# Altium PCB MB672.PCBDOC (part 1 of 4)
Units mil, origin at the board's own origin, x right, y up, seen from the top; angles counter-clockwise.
Board outline 4505 x 6805 mil, 4 copper layers (TopLayer, GND, VCC, BottomLayer); 337 components, 289 nets, 1516 pads, 621 vias.
Unrouted connection lines stored in the file: 46.
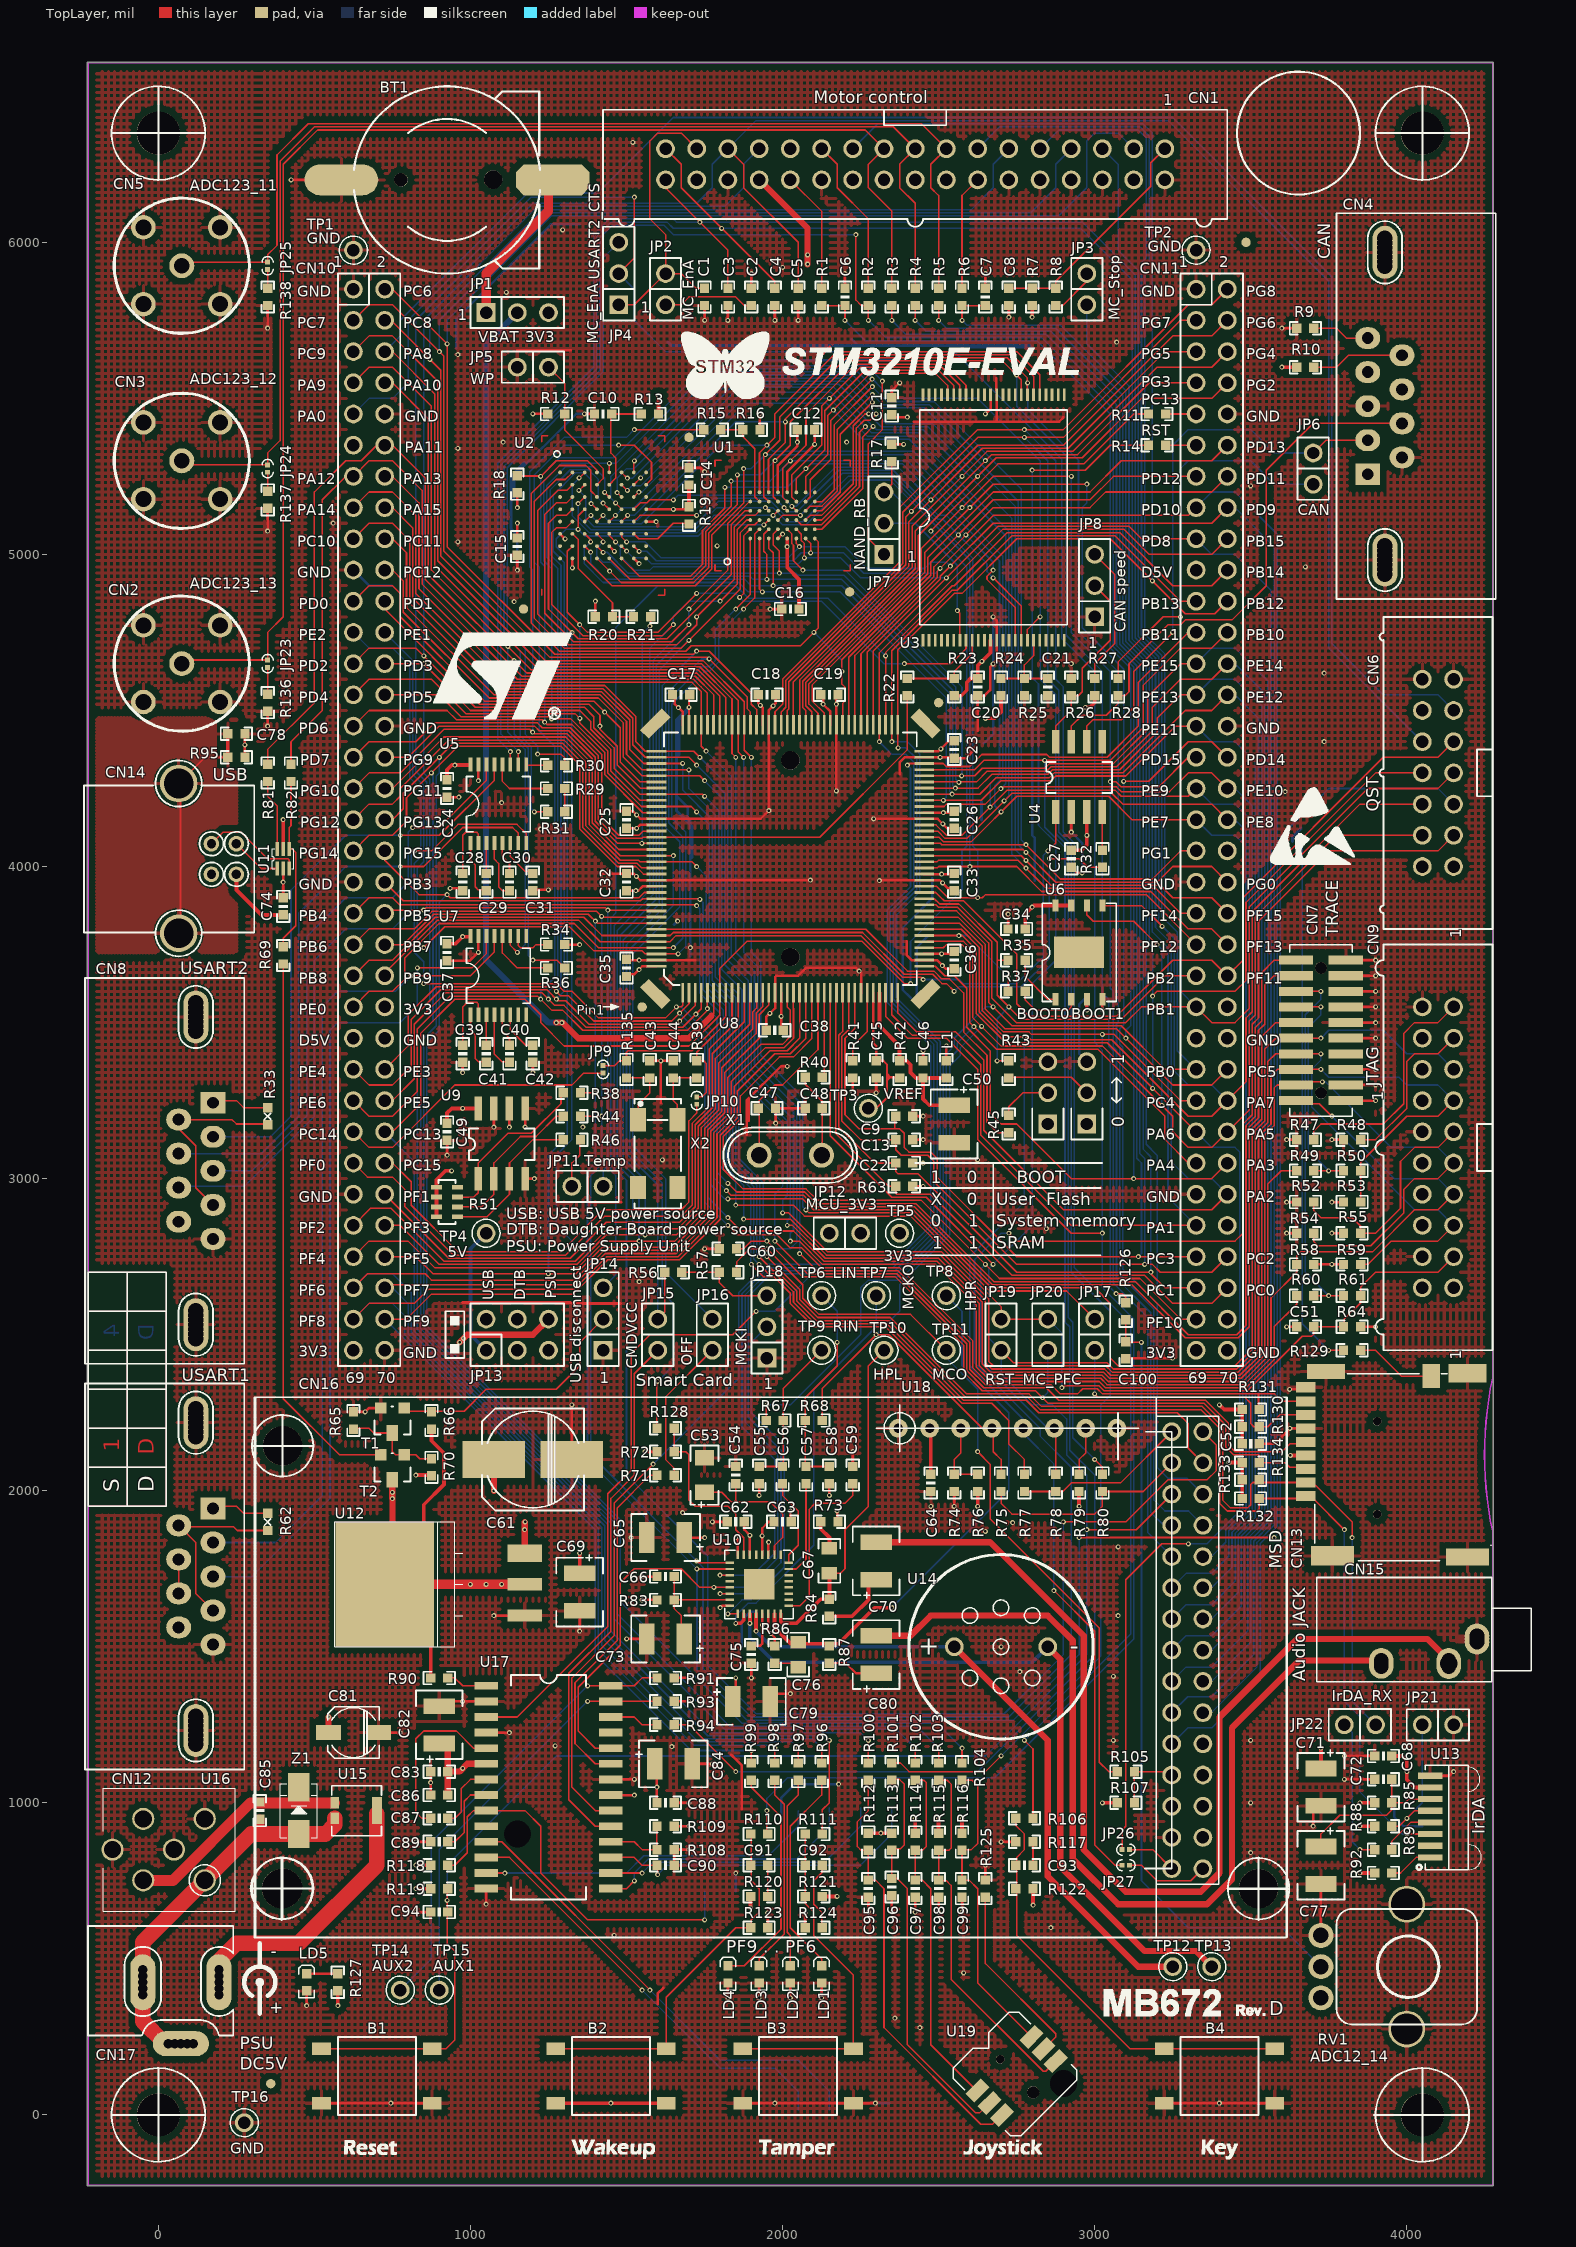
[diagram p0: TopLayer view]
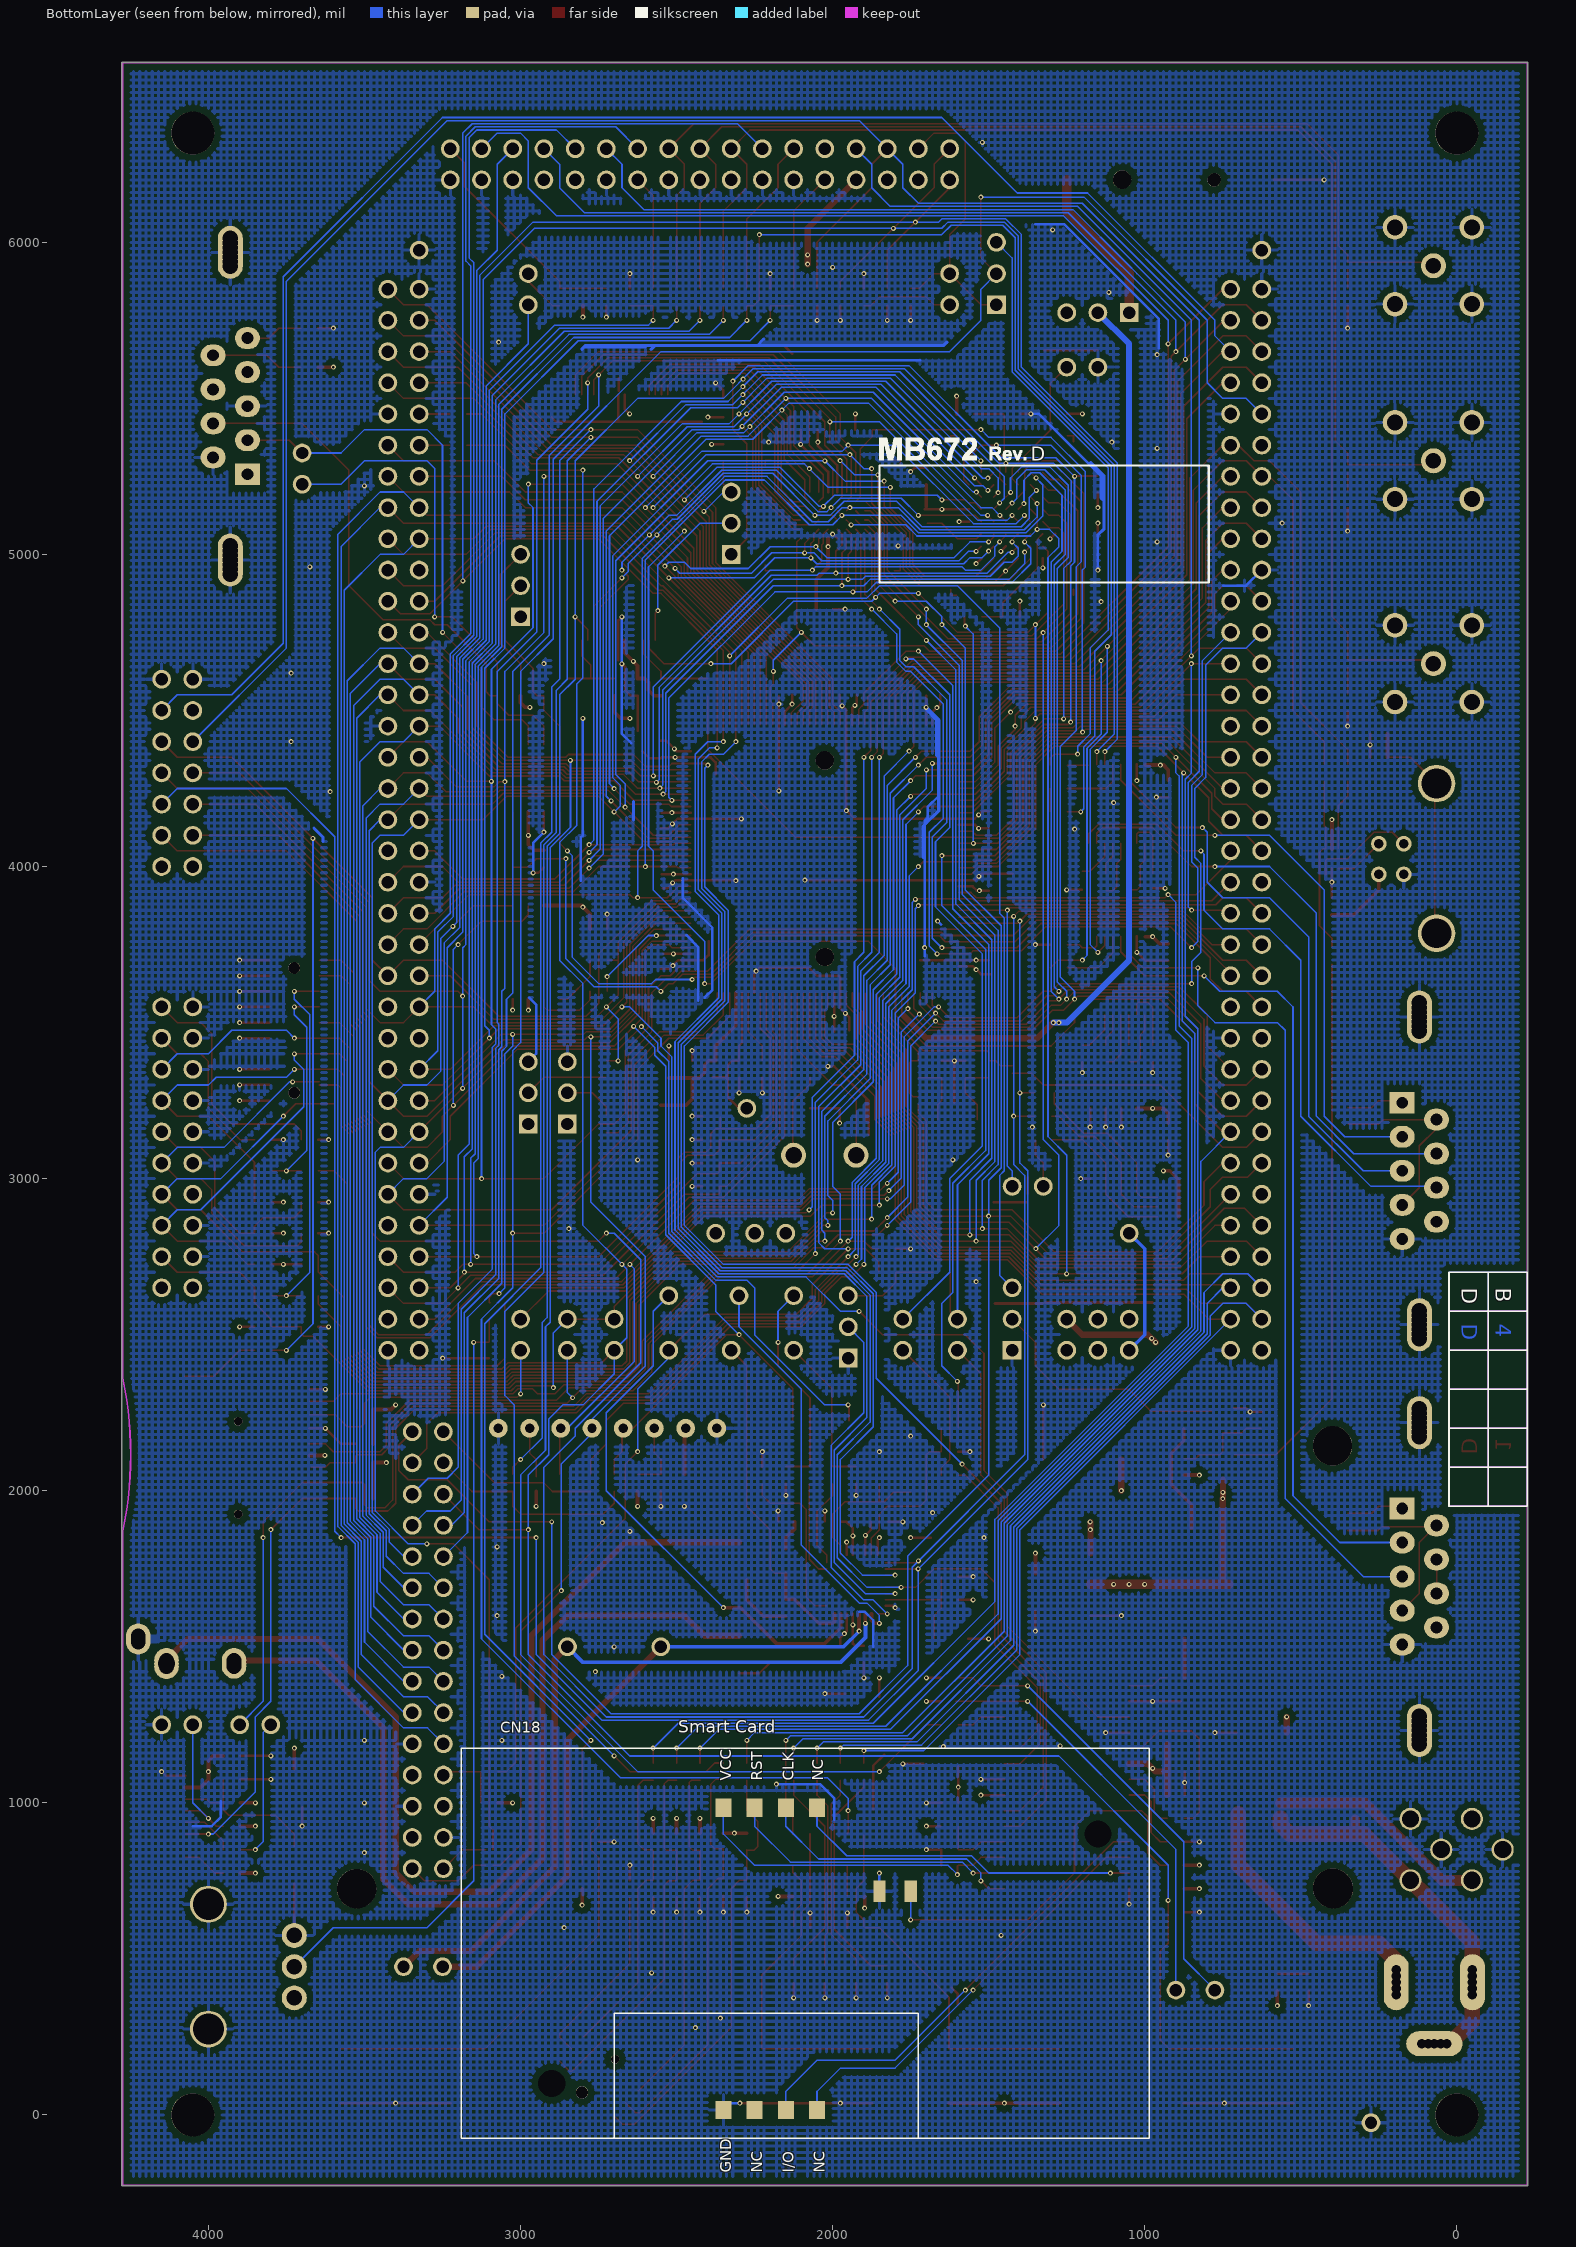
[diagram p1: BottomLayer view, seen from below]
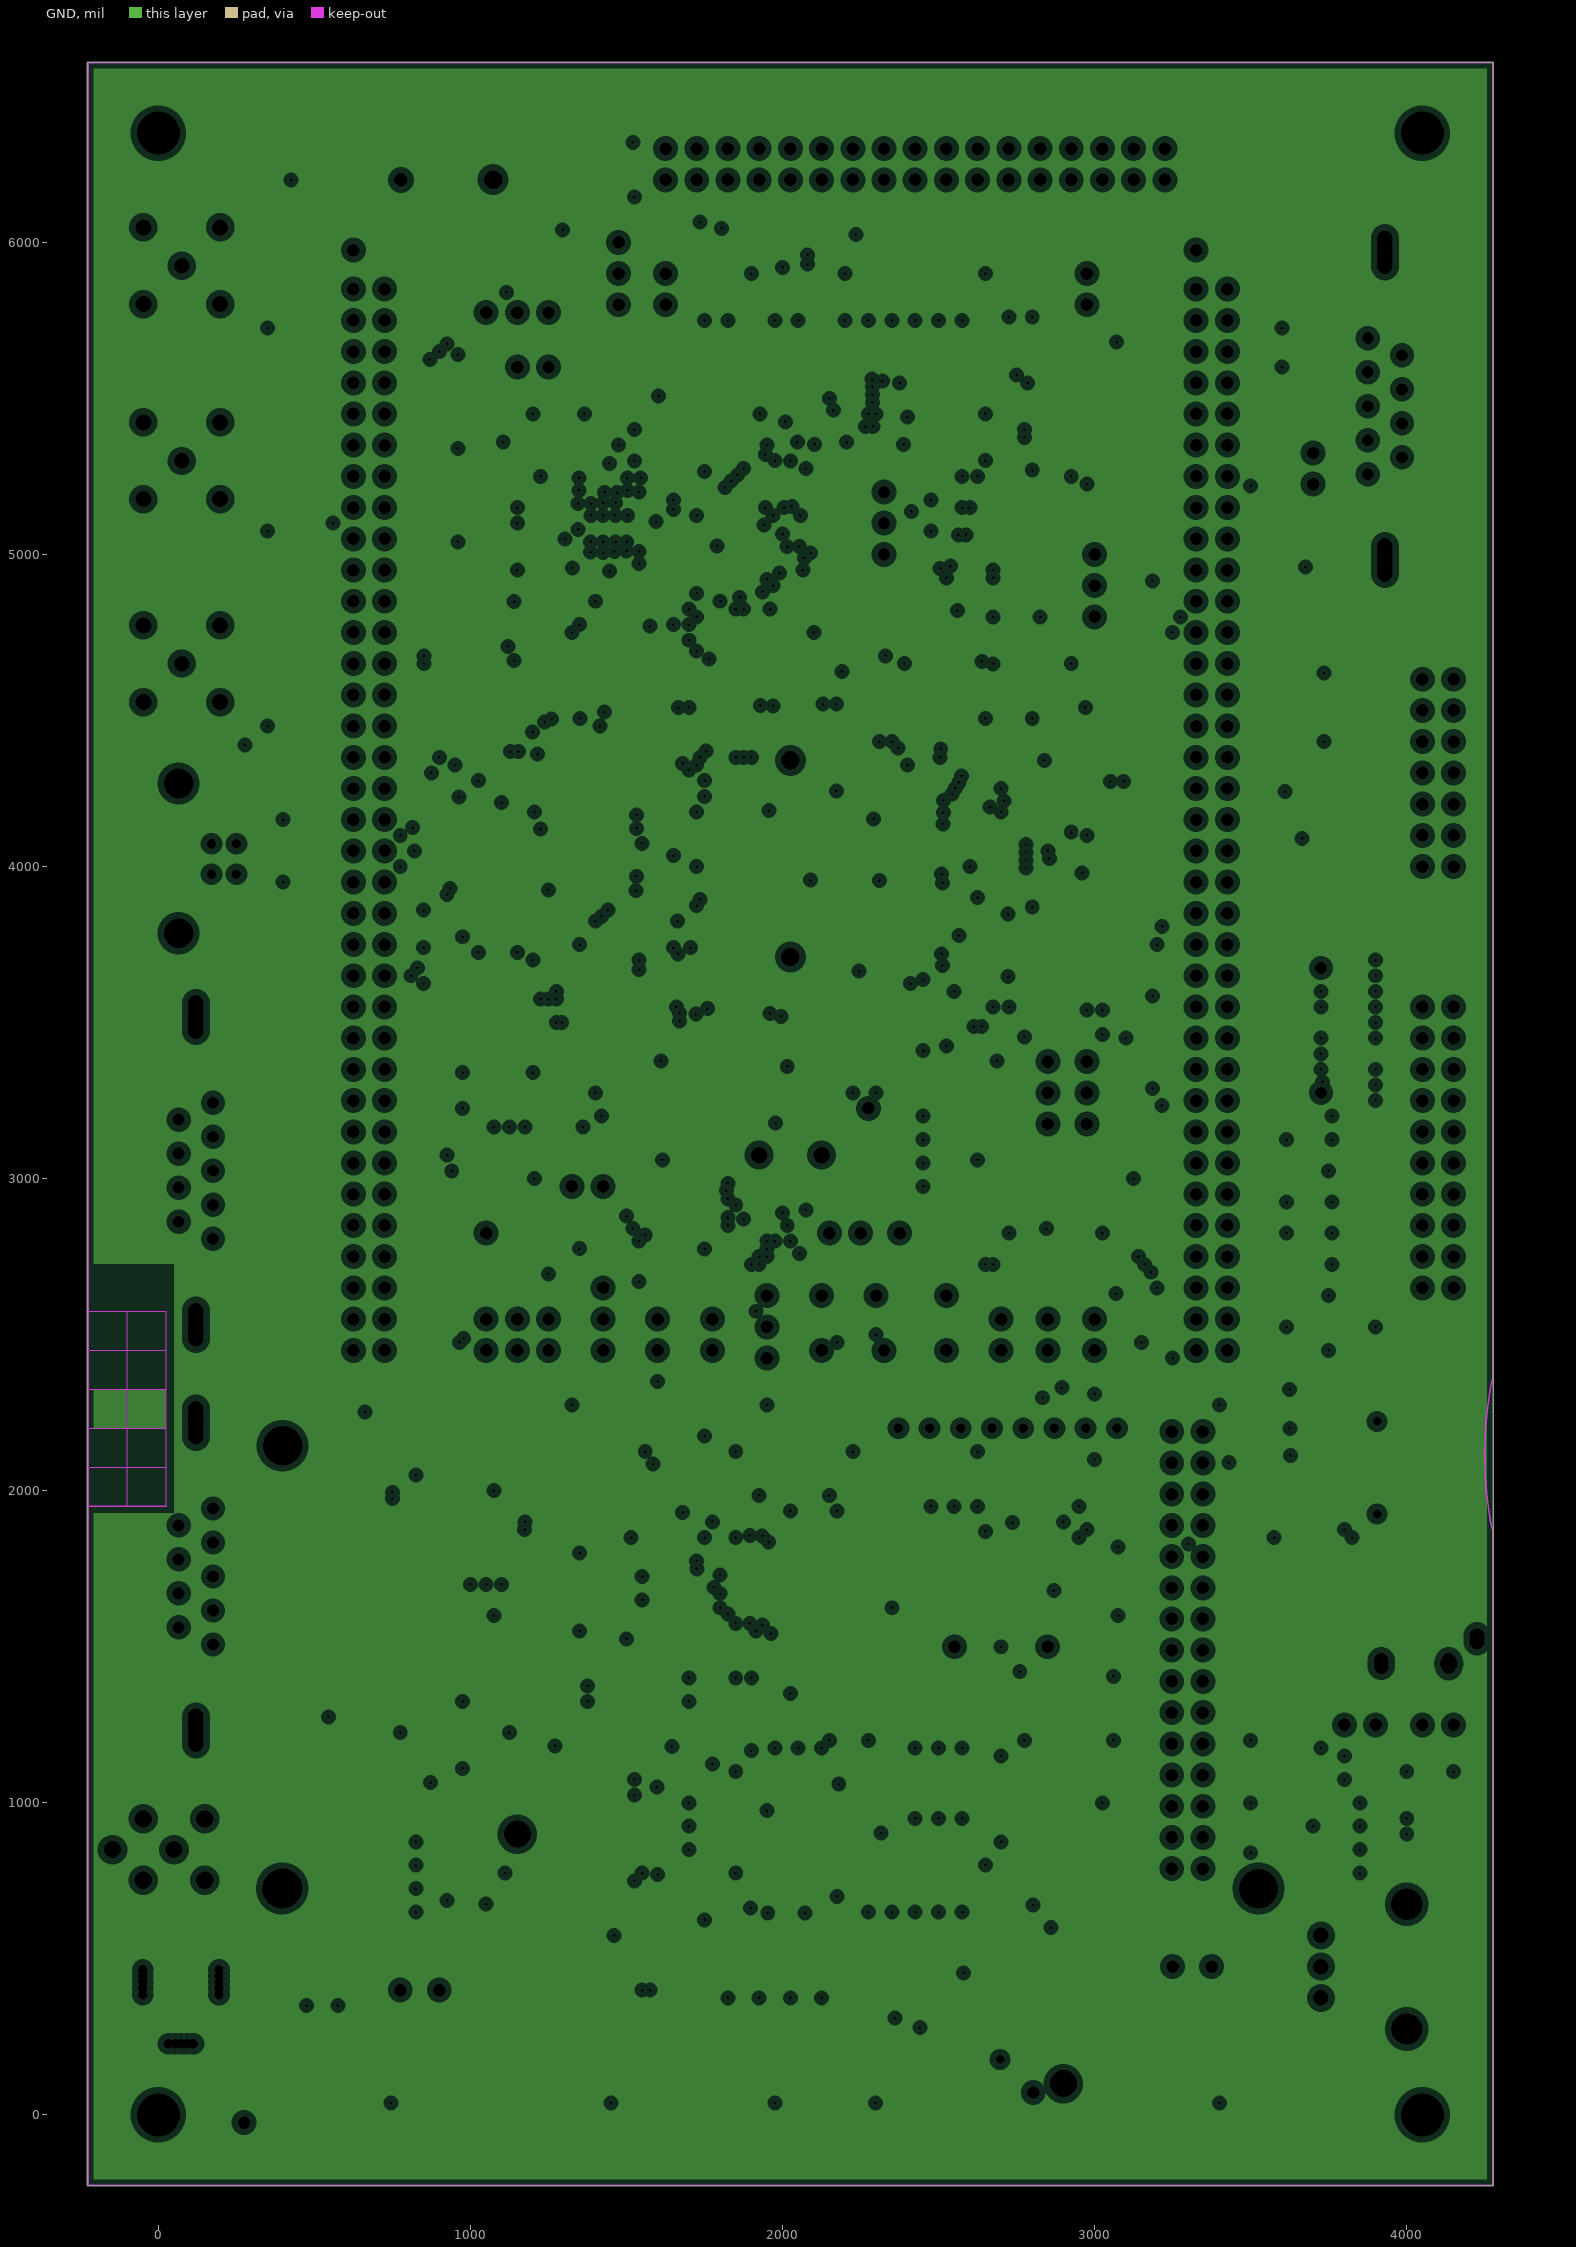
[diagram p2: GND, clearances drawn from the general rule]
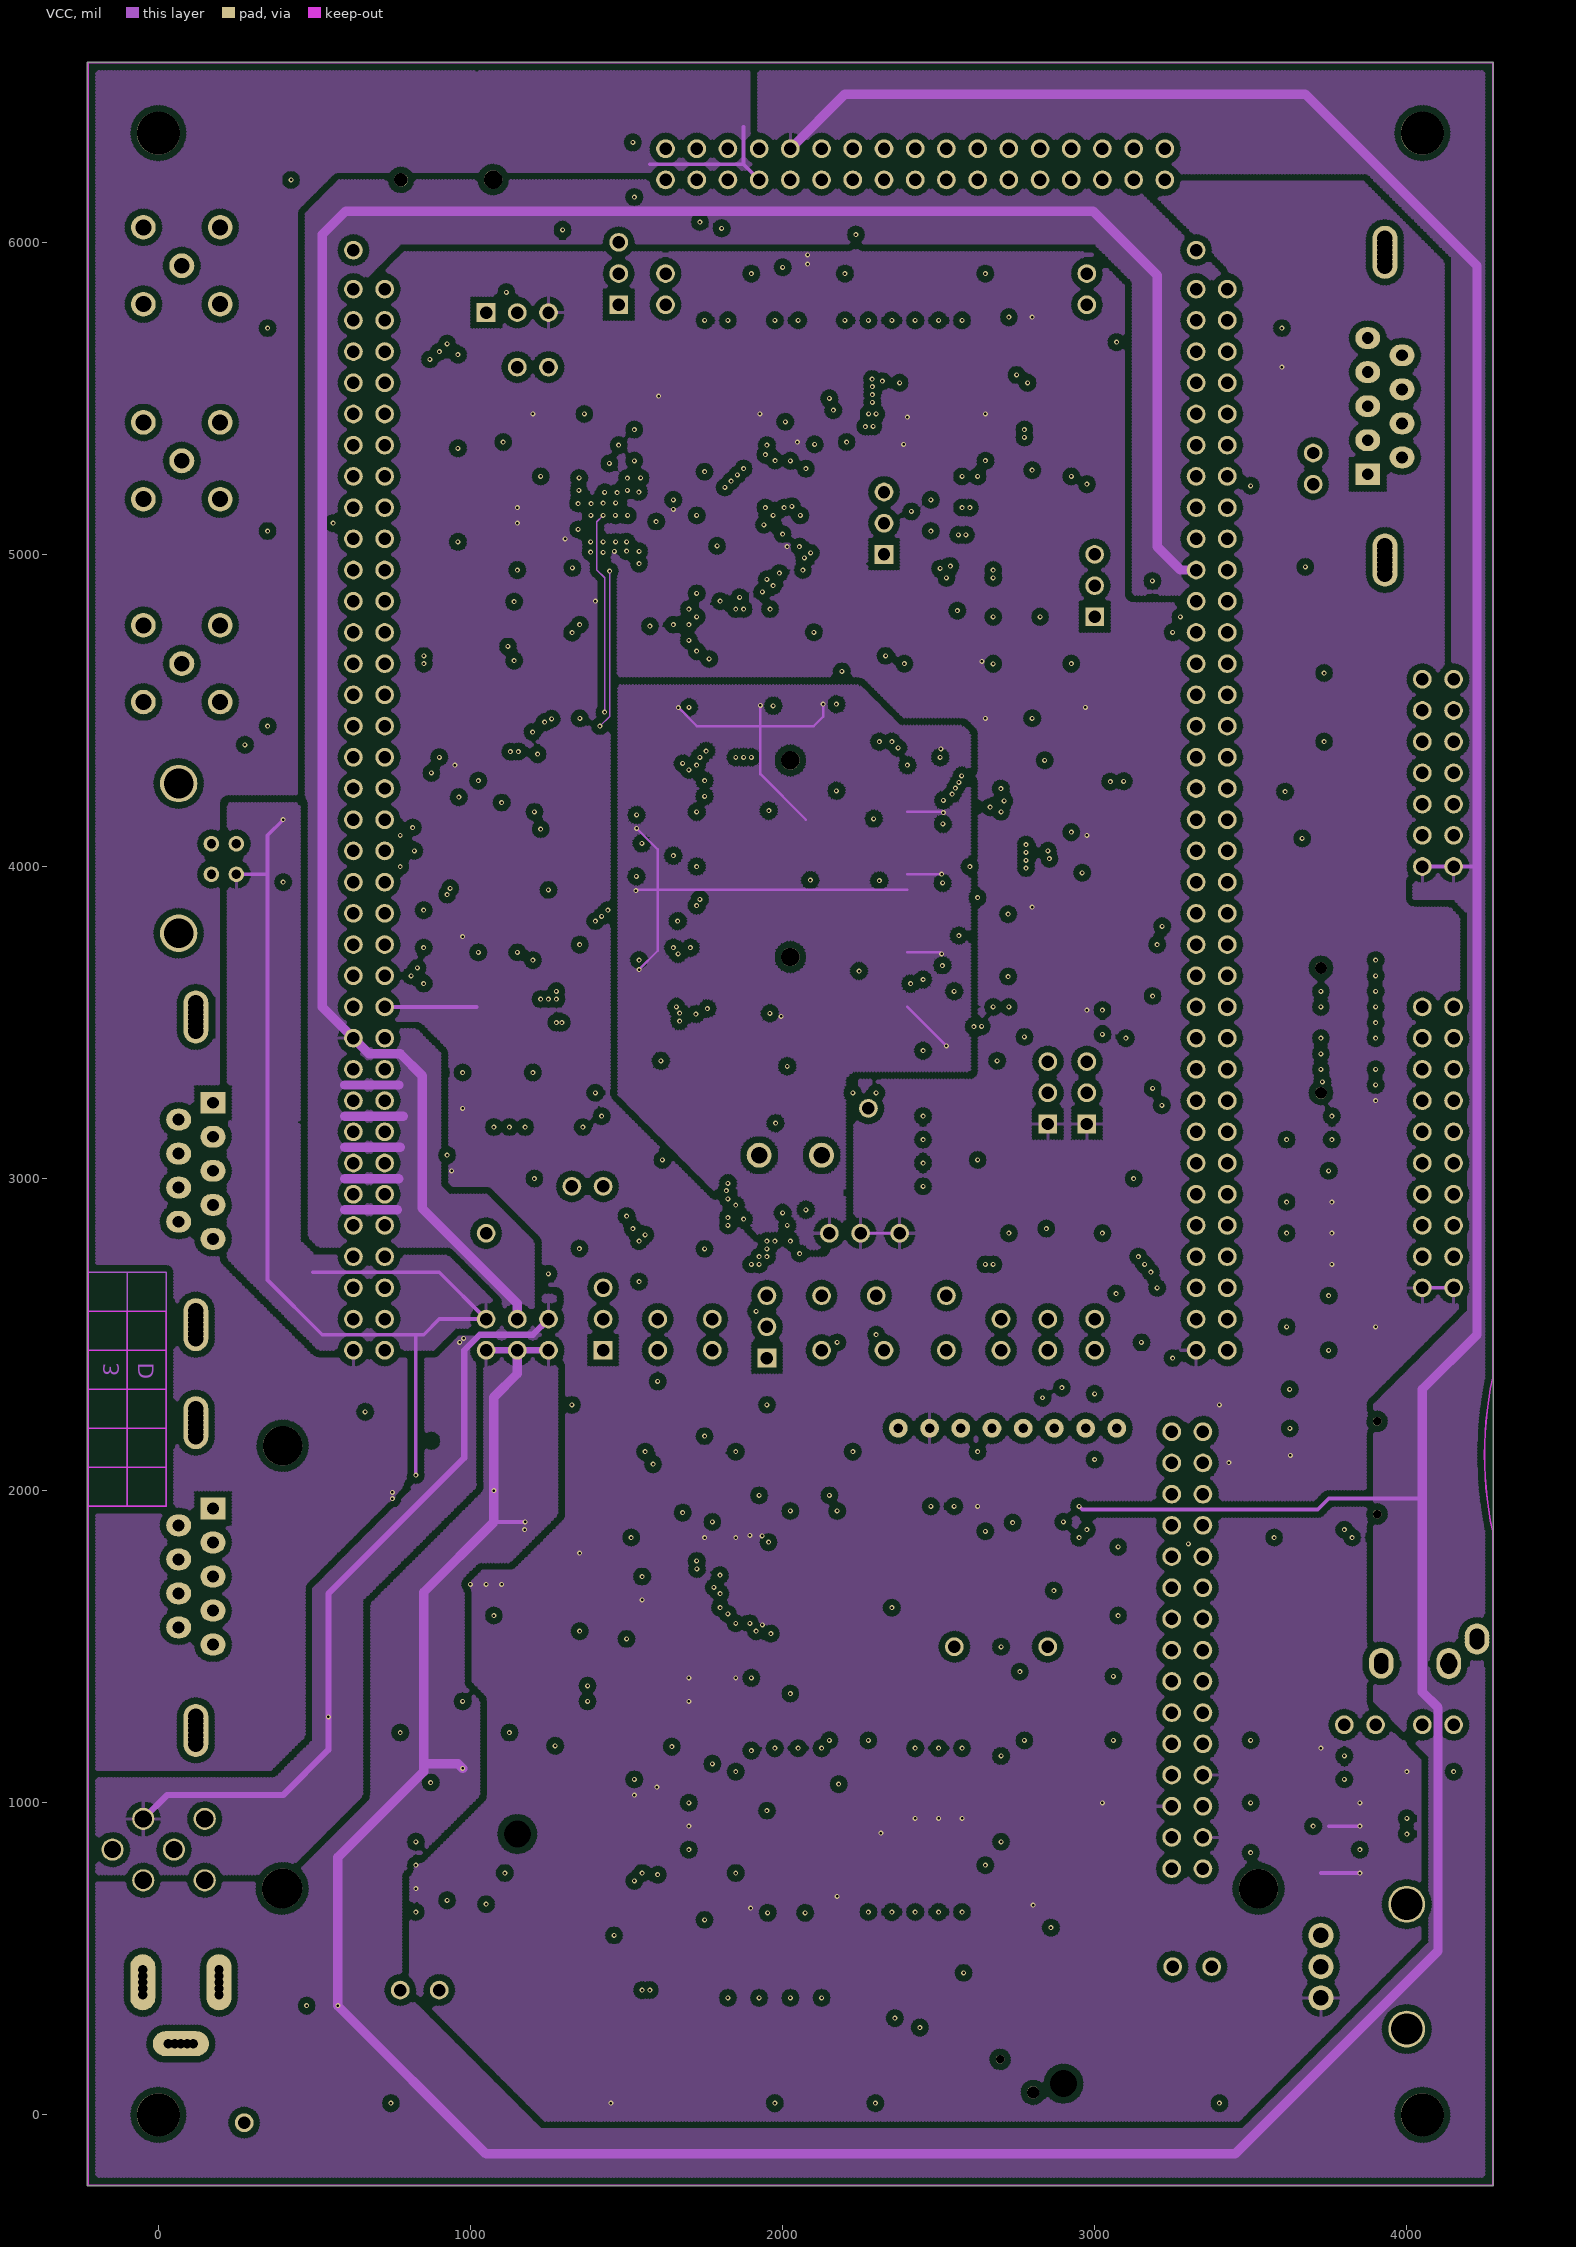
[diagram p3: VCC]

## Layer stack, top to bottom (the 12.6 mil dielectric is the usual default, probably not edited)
TopSolder: solder mask 0.4, Solder Resist, Dk 3.5
TopLayer: signal copper 1.4
Dielectric1: core 12.6, FR-4, Dk 4.8
GND: plane copper 1.4
Dielectric3: prepreg 12.6, FR-4, Dk 4.8
VCC: signal copper 1.4
Dielectric2: core 12.6, FR-4, Dk 4.8
BottomLayer: signal copper 1.4
BottomSolder: solder mask 0.4, Solder Resist, Dk 3.5

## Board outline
-227.5,-227.5 4277.5,-227.5 4277.5,6577.5 -227.5,6577.5

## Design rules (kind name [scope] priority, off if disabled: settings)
Clearance Clearance_1 [(InPoly)] p1: gap=20 ignorepadtopadclearanceinfootprint=FALSE except(0: Arc-Hole Track-Hole SMDPad-Hole THPad-Hole Via-Hole Fill-Hole Poly-Hole Region-Hole Text-Hole) // Protel DXP Scope 1 Expression Was: (InPoly)   Protel DXP Scope 1 Expression Was: (InPoly)
Clearance [All] p2: gap=5 ignorepadtopadclearanceinfootprint=FALSE except(0: Arc-Hole Track-Hole SMDPad-Hole THPad-Hole Via-Hole Fill-Hole Poly-Hole Region-Hole Text-Hole)
ComponentClearance [All] p1 off: gap=10 collisioncheckmode=3 verticalgap=10 showdistances=FALSE
FabricationTestPointUsage TestPointUsage [All] p1: valid=0 allowmultiple=FALSE
FabricationTestpoint Testpoint [All] p1: side=3 testpointundercomponent=TRUE minsize=40 maxsize=100 preferedsize=60 minholesize=20 maxholesize=40 preferedholesize=32 testpointgrid=1 allowsidetop=TRUE allowsidebottom=TRUE usegrid=TRUE gridtolerance=0.01
PlaneClearance [All] p1: clearance=20
PlaneConnect [All] p1: planeconnectstyle=Relief reliefexpansion=20 reliefentries=4 reliefconductorwidth=10 reliefairgap=10
PolygonConnect [All] p1: connectstyle=Relief reliefconductorwidth=10 reliefentries=4 polygonreliefangle="90 Angle" airgapwidth=10
RoutingLayers [All] p1: top layer_v5=TRUE mid layer 1_v5=FALSE bottom layer_v5=TRUE
RoutingVias [All] p1: holewidth=8 width=16 viastyle="Through Hole" minholewidth=5 minwidth=8 maxholewidth=28 maxwidth=50
SolderMaskExpansion [All] p1: expansion=4 istentingtop=FALSE
Width Width_3 [InNet('D5V')] p1: maxlimit=300 minlimit=7 preferedwidth=30
Width Width_4 [InNet('E5V')] p2: maxlimit=300 minlimit=7 preferedwidth=20
Width Width_1 [InNet('+3V3')] p3: maxlimit=300 minlimit=7 preferedwidth=12
Width Width_2 [InNet('+5V')] p4: maxlimit=300 minlimit=7 preferedwidth=30
Width Width_7 [InNet('VDD')] p5: maxlimit=300 minlimit=7 preferedwidth=8
Width Width_8 [InNet('VDDA')] p6: maxlimit=300 minlimit=7 preferedwidth=12
Width Width_5 [InNet('GND')] p7: maxlimit=300 minlimit=7 preferedwidth=10
Width Width_6 [InNet('U5V')] p8: maxlimit=300 minlimit=7 preferedwidth=12
Width [All] p9: maxlimit=300 minlimit=5 preferedwidth=5
24 further rules are at their usual default settings.

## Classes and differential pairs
net class A[0..23]: A0 A1 A2 A3 A4 A5 A6 A7 A8 A9 A10 A11 A12 A13 A14 A15 A16 A17 A18 A19 A20 A21 A22 A23 A[0..23]0 A[0..23]1 A[0..23]2 A[0..23]3 A[0..23]4 A[0..23]5 A[0..23]6 A[0..23]7 A[0..23]8 A[0..23]9 A[0..23]10 A[0..23]11 A[0..23]12 A[0..23]13 A[0..23]14 A[0..23]15 A[0..23]16 A[0..23]17 A[0..23]18 A[0..23]19 A[0..23]20 A[0..23]21 A[0..23]22 A[0..23]23
net class D[0..15]: D0 D1 D2 D3 D4 D5 D6 D7 D8 D9 D10 D11 D12 D13 D14 D15 D[0..15]0 D[0..15]1 D[0..15]2 D[0..15]3 D[0..15]4 D[0..15]5 D[0..15]6 D[0..15]7 D[0..15]8 D[0..15]9 D[0..15]10 D[0..15]11 D[0..15]12 D[0..15]13 D[0..15]14 D[0..15]15
net class A[0..25]: A0 A1 A2 A3 A4 A5 A6 A7 A8 A9 A10 A11 A12 A13 A14 A15 A16 A17 A18 A21 A22 A[0..25]0 A[0..25]1 A[0..25]2 A[0..25]3 A[0..25]4 A[0..25]5 A[0..25]6 A[0..25]7 A[0..25]8 A[0..25]9 A[0..25]10 A[0..25]11 A[0..25]12 A[0..25]13 A[0..25]14 A[0..25]15 A[0..25]16 A[0..25]17 A[0..25]18 A[0..25]19 A[0..25]20 A[0..25]21 A[0..25]22 A[0..25]23 A[0..25]24 A[0..25]25 D0 D1 PD3 PG13 PG14
component class MotorCtrl_2: C17 C18 C19 C23 C25 C26 C33 C35 C36 C38 CN6 JP26 R34 R56 R57 R75 R131 R132 R133 R134
component class SRAM&Flash: C10 C20 C21 C24 C62 C63 C75 C88 JP2 JP5 JP6 JP7 R12 R13 R17 R19 R20 R23 R24 U1 U2
component class CFcard: C21 C24 C63 CN14 R12 R13 R17 R20 R26 R32 R35 R37 R38 R126 U1
net class PE[0..15]: A19 A20 A21 A22 A23 NetR73_2 NetR74_2 PE7 PE8 PE9 PE10 PE11 PE12 PE13 PE14 PE15 PE[0..15]0 PE[0..15]1 PE[0..15]2 PE[0..15]3 PE[0..15]4 PE[0..15]5 PE[0..15]6 PE[0..15]7 PE[0..15]8 PE[0..15]9 PE[0..15]10 PE[0..15]11 PE[0..15]12 PE[0..15]13 PE[0..15]14 PE[0..15]15
net class PD[0..15]: NetR72_2 NetR75_2 NetU14_4 NetU14_5 PB14 PD0 PD1 PD2 PD3 PD4 PD5 PD6 PD10 PD11 PD13 PD[0..15]0 PD[0..15]1 PD[0..15]2 PD[0..15]3 PD[0..15]4 PD[0..15]5 PD[0..15]6 PD[0..15]7 PD[0..15]8 PD[0..15]9 PD[0..15]10 PD[0..15]11 PD[0..15]12 PD[0..15]13 PD[0..15]14 PD[0..15]15 PG7
net class PC[0..15]: PC0 PC1 PC2 PC3 PC4 PC5 PC6 PC7 PC8 PC9 PC10 PC11 PC12 PC13 PC14 PC15 PC[0..15]0 PC[0..15]1 PC[0..15]2 PC[0..15]3 PC[0..15]4 PC[0..15]5 PC[0..15]6 PC[0..15]7 PC[0..15]8 PC[0..15]9 PC[0..15]10 PC[0..15]11 PC[0..15]12 PC[0..15]13 PC[0..15]14 PC[0..15]15
net class PB[0..15]: NetU15_5 PB0 PB1 PB2 PB3 PB4 PB5 PB8 PB10 PB11 PB12 PB13 PB14 PB[0..15]0 PB[0..15]1 PB[0..15]2 PB[0..15]3 PB[0..15]4 PB[0..15]5 PB[0..15]6 PB[0..15]7 PB[0..15]8 PB[0..15]9 PB[0..15]10 PB[0..15]11 PB[0..15]12 PB[0..15]13 PB[0..15]14 PB[0..15]15 PG8 TEMPERATURESENSOR_SCL TEMPERATURESENSOR_SDA
net class PA[0..15]: PA0 PA1 PA2 PA3 PA4 PA5 PA6 PA7 PA8 PA9 PA10 PA11 PA12 PA13 PA14 PA15 PA[0..15]0 PA[0..15]1 PA[0..15]2 PA[0..15]3 PA[0..15]4 PA[0..15]5 PA[0..15]6 PA[0..15]7 PA[0..15]8 PA[0..15]9 PA[0..15]10 PA[0..15]11 PA[0..15]12 PA[0..15]13 PA[0..15]14 PA[0..15]15
component class Extension: CN1 CN17 R96 R97
component class JTAG&SWD: CN7 CN9 CN18 JP19 R47 R48 R49 R50 R52 R53 R54 R55 R58 R59 R60 R61 R64
component class MotorCtrl: C5 C28 C37 C51 C60 C61 C64 C92 C93 C97 C98 C99 CN8 JP5 JP20 R9 R15 R56 R81 R82 R93 R98 R101
component class MCU: B1 BOOT0 BOOT1 BT1 C1 C3 C4 C5 C9 C13 C51 C59 C67 C70 C76 C80 JP7 L1 R20 R71 R84 R87 R115 R116 R117 R124 TP10 U10 X1 X2
component class Peripherals: C14 C27 C49 C74 C78 CN3 CN11 CN14 JP6 JP8 JP14 LD2 LD3 LD4 LD5 R9 R10 R11 R15 R26 R27 R28 R32 R35 R37 R38 R44 R46 R51 R56 R59 R65 R66 R69 R70 R93 R95 R96 R97 R98 R99 R101 R105 R107 R109 R119 R126 RV1 T1 T2 TR1 TR2 U4 U6 U9 U11
component class Power: C11 C61 C69 C81 C85 CN17 JP13 LD1 R127 TP4 TP5 TP16 U12 U15 U16 Z1
component class RS232&IrDA: C28 C29 C30 C31 C37 C39 C40 C41 C42 C52 C68 C71 C72 C77 CN8 CN12 JP21 R29 R30 R33 R36 R62 R85 R88 R89 R92 U5 U7 U13
component class Audio: C20 C21 C24 C62 C63 C75 C88 C91 CN4 JP11 JP16 R13 R17 R19 R20 R23 R24 R26 R32 R35 R37 R38 R64 R101 R126 RV2 RV3 TP4 TP5 TP15 TP16 U9 U15 U18 U19
component class LCD&Joystick: B1 B2 B4 C64 C91 C92 C93 C95 C96 C97 C98 C99 R52 R54 R74 R76 R79 R100 R101 R102 R103 R104 R106 R110 R111 R112 R113 R114 R115 R116 R117 R120 R121 R122 R123 R124 R125 U15 U18 U19
component class MC&Extension: C5 C28 C37 C60 C61 C64 C92 C93 C97 C98 C99 CN1 CN8 CN17 JP20 R9 R15 R56 R81 R82 R96 R97 R98 R101
component class SD&SmartCard: C5 C51 C60 C69 C81 C85 CN7 CN12 R33 R53 R60 R62 R85 R88 R92 R110 R112 R114 R123 TP8 TP9 U16
component class Debug: CN5 CN7 CN9 CN18 JP19 R47 R48 R52 R53 R54 R55 R58 R59

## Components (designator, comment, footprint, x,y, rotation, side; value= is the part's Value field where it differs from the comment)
B1 "RESET" PB10 700,125 r90 top
B2 "WKUP" PB10 1450,125 r90 top
B3 "Tamper" PB10 2050,125 r90 top
B4 "USER" PB10 3400,125 r90 top
BOOT0 "" SIP3 2850,3175 r90 top
BOOT1 "" SIP3 2975,3175 r90 top
BT1 "Battery holder" LI1220_1 925,6200 r90 top
C1 "do not fit" 0603 1750,5825 r90 top
C2 "10nF" 0603 1900,5825 r270 top
C3 "do not fit" 0603 1825,5825 r90 top
C4 "do not fit" 0603 1975,5825 r90 top
C5 "do not fit" 0603 2050,5825 r90 top
C6 "100nF" 0603P 2200,5825 r270 top
C7 "100nF" 0603P 2650,5825 r270 top
C8 "1nF" 0603 2725,5825 r90 top
C9 "do not fit" 0603 2390,3200 r180 top
C10 "100nF" 0603P 1425,5450 r180 top
C11 "100nF" 0603P 2350,5475 r90 top
C12 "100nF" 0603P 2075,5400 r0 top
C13 "do not fit" 0603 2390,3125 r180 top
C14 "100nF" 0603P 1700,5250 r270 top
C15 "100nF" 0603P 1150,5025 r90 top
C16 "100nF" 0603P 2025,4825 r180 top
C17 "100nF" 0603P 1675,4550 r0 top
C18 "100nF" 0603P 1950,4550 r0 top
C19 "100nF" 0603P 2150,4550 r0 top
C20 "100nF" 0603P 2625,4575 r90 top
C21 "100nF" 0603P 2850,4575 r90 top
C22 "do not fit" 0603 2390,3050 r180 top
C23 "100nF" 0603p 2550,4375 r270 top
C24 "100nF" 0603P 925,4250 r90 top
C25 "100nF" 0603P 1500,4150 r90 top
C26 "100nF" 0603P 2550,4150 r270 top
C27 "100nF" 0603P 2925,4025 r90 top
C28 "100nF" 0603P 975,3950 r90 top
C29 "100nF" 0603P 1050,3950 r90 top
C30 "100nF" 0603P 1125,3950 r90 top
C31 "100nF" 0603P 1200,3950 r90 top
C32 "100nF" 0603P 1500,3950 r90 top
C33 "100nF" 0603P 2550,3950 r270 top
C34 "100nF" 0603P 2750,3800 r0 top
C35 "100nF" 0603P 1500,3675 r90 top
C36 "100nF" 0603P 2550,3700 r270 top
C37 "100nF" 0603P 925,3725 r270 top
C38 "100nF" 0603p 1975,3475 r180 top
C39 "100nF" 0603P 975,3400 r90 top
C40 "100nF" 0603P 1125,3400 r90 top
C41 "100nF" 0603P 1050,3400 r90 top
C42 "100nF" 0603P 1200,3400 r90 top
C43 "10pF" 0603 1575,3350 r90 top
C44 "10pF" 0603 1650,3350 r90 top
C45 "10nF" 0603 2300,3350 r270 top
C46 "10nF" 0603 2450,3350 r270 top
C47 "20pF" 0603 1950,3225 r0 top
C48 "20pF" 0603 2100,3225 r180 top
C49 "100nF" 0603P 925,3150 r90 top
C50 "10uF" TAN-B 2550,3175 r270 top
C51 "do not fit" 0603 3675,2525 r0 top
C52 "100nF" 0603P 3500,2150 r0 top
C53 "2.2uF" TAN-A 1750,2050 r90 top
C54 "100nF" 0603P 1850,2050 r90 top
C55 "do not fit" 0603 1925,2050 r90 top
C56 "1uF" 0603 2000,2050 r90 top
C57 "1uF" 0603 2075,2050 r90 top
C58 "do not fit" 0603 2150,2050 r90 top
C59 "1uF" 0603 2225,2050 r90 top
C60 "do not fit" 0603 1825,2775 r0 top
C61 "220uF" C310M 1200,2100 r180 top
C62 "100nF" 0603P 1850,1900 r0 top
C63 "100nF" 0603P 2000,1900 r180 top
C64 "100nF" 0603P 2475,2025 r270 top
C65 "10uF" TAN-B 1625,1850 r180 top
C66 "100nF" 0603P 1625,1725 r180 top
C67 "0.22uF" 0805 2150,1775 r180 top
C68 "0.1uF" 0603P 3925,1150 r180 top
C69 "47uF" TAN-B 1350,1675 r270 top
C70 "47uF" TAN-B 2300,1775 r90 top
C71 "4.7uF" TAN-B 3725,1050 r270 top
C72 "0.1uF" 0603P 3925,1075 r180 top
C73 "10uF" TAN-B 1625,1525 r180 top
C74 "100nF" 0603P 400,3872.5 r270 top
C75 "100nF" 0603P 1900,1475 r90 top
C76 "0.22uF" 0805 2050,1475 r0 top
C77 "4.7uF" TAN-B 3725,800 r270 top
C78 "4.7nF" 0603 250,4425 r180 top
C79 "10uF" TAN-B 1900,1325 r0 top
C80 "47uF" TAN-B 2300,1475 r90 top
C81 "10uF" C160M 625,1225 r180 top
C82 "47uF" TAN-B 900,1250 r90 top
C83 "100nF" 0603P 900,1100 r180 top
C84 "47uF" TAN-B 1650,1125 r0 top
C85 "100nF" 0603P 325,975 r270 top
C86 "330nF" 0603 900,1025 r180 top
C87 "100nF" 0603P 900,950 r180 top
C88 "100nF" 0603p 1625,1000 r180 top
C89 "100nF" 0603P 900,875 r180 top
C90 "100nF" 0603P 1625,800 r180 top
C91 "do not fit" 0603 1925,800 r180 top
C92 "100nF" 0603P 2100,800 r180 top
C93 "100nF" 0603P 2775,800 r180 top
C94 "100nF" 0603P 900,650 r0 top
C95 "100nF" 0603P 2275,725 r90 top
C96 "100nF" 0603P 2350,730 r90 top
C97 "100nF" 0603P 2425,725 r90 top
C98 "100nF" 0603P 2500,725 r90 top
C99 "100nF" 0603P 2575,725 r90 top
C100 "10nF" 0603 3100,2450 r90 top
CN1 "MC_connector" IDC34S 3225,6300 r270 top locked
CN2 "BNC-KE-47" VB334 75,4650 r0 top
CN3 "BNC-KE-47" VB334 75,5300 r270 top
CN4 "DB9-male CAN connector" DB9/M 3875,5475 r270 top
CN5 "BNC-KE-47" VB334 75,5925 r0 top
CN6 "Header 7X2" IDC14S 4150,4000 r180 top
CN7 "Header 10x2" FTSH-110-01-L-DV 3725,3475 r90 top
CN8 "DB9-male USART2" DB9/M 175,3025 r90 top
CN9 "JTAG" IDC20S 4150,2650 r180 top locked
CN10 "Header 35X2" 2*35P 625,5850 r0 top locked
CN11 "Header 35X2" 2*35P 3325,5850 r0 top locked
CN12 "DB9-male USART1" DB9/M 175,1725 r90 top
CN13 "PJS008-2003-1" MSD(PJS008) 3905,1925 r0 top
CN14 "USB-typeB connector" USB-B 250,3975 r270 top
CN15 "Audio jack" ST-225-02 4225,1525 r180 top
CN16 "Connector to Mother board" AM240*320B 3525,725 r0 top
CN17 "DC-005-2.5" DC10B -50,425 r0 top
CN18 "C816" SAM(C816) 2025,500 r270 bottom
JP1 "" SIP3 1050,5775 r0 top
JP2 "" SIP2 1625,5900 r270 top
JP3 "" SIP2 2975,5800 r90 top
JP4 "" SIP3 1475,5800 r90 top
JP5 "" SIP2 1150,5600 r0 top
JP6 "" SIP2 3700,5225 r90 top
JP7 "" SIP3 2325,5000 r90 top
JP8 "" SIP3 3000,4800 r90 top
JP9 "" JP2_SMD 1425,3350 r270 top
JP10 "" JP2_SMD 1725,3250 r90 top
JP11 "" SIP2 1425,2975 r180 top
JP12 "" SIP2 2150,2825 r0 top
JP13 "" 2*3P 1050,2450 r90 top
JP14 "" SIP3 1425,2450 r90 top
JP15 "" SIP2 1600,2550 r270 top
JP16 "" SIP2 1775,2550 r270 top
JP17 "" SIP2 3000,2550 r270 top
JP18 "" SIP3 1950,2425 r90 top
JP19 "" SIP2 2700,2550 r270 top
JP20 "" SIP2 2850,2450 r90 top
JP21 "" SIP2 4050,1250 r0 top
JP22 "" SIP2 3900,1250 r180 top
JP23 "" JP2_SMD 350,4650 r270 top
JP24 "" JP2_SMD 350,5275 r270 top
JP25 "" JP2_SMD 350,5925 r270 top
JP26 "" JP2_SMD 3100,850 r0 top
JP27 "" JP2_SMD 3100,800 r0 top
L1 "BEAD" 0603 2525,3350 r90 top
LD1 "Green" D0603 2125,450 r0 top
LD2 "Orange" D0603 2025,450 r0 top
LD3 "Red" D0603 1925,450 r0 top
LD4 "Blue" D0603 1825,450 r0 top
LD5 "red" D0603 475,425 r0 top
R1 "0" 0603 2125,5825 r270 top
R2 "do not fit" 0603 2275,5825 r90 top
R3 "0" 0603 2350,5825 r90 top
R4 "0" 0603 2425,5825 r90 top
R5 "0" 0603 2500,5825 r90 top
R6 "0" 0603 2575,5825 r270 top
R7 "3.3K" 0603 2800,5825 r270 top
R8 "0" 0603 2875,5825 r270 top
R9 "0" 0603 3675,5725 r0 top
R10 "do not fit" 0603 3675,5600 r0 top
R11 "820" 0603 3200,5450 r0 top
R12 "10K" 0603 1275,5450 r0 top
R13 "10K" 0603 1575,5450 r0 top
R14 "820" 0603 3200,5350 r180 top
R15 "0" 0603 1775,5400 r0 top
R16 "10K" 0603 1900,5400 r180 top
R17 "10K" 0603 2350,5325 r90 top
R18 "10K" 0603 1150,5225 r270 top
R19 "10K" 0603 1700,5125 r270 top
R20 "10K" 0603 1427.5,4800 r180 top
R21 "0" 0603 1550,4800 r180 top
R22 "0" 0603 2400,4575 r90 top
R23 "10K" 0603 2550,4575 r270 top
R24 "10K" 0603 2700,4575 r90 top
R25 "do not fit" 0603 2775,4575 r270 top
R26 "10K" 0603 2925,4575 r90 top
R27 "0" 0603 3000,4575 r270 top
R28 "120" 0603 3075,4575 r90 top
R29 "0" 0603 1275,4250 r0 top
R30 "0" 0603 1275,4325 r0 top
R31 "0" 0603 1275,4175 r0 top
R32 "0" 0603 3025,4025 r270 top
R33 "do not fit" 0603_NC 350,3200 r90 top
R34 "10K" 0603 1275,3750 r0 top
R35 "0" 0603 2750,3700 r180 top
R36 "0" 0603 1275,3675 r0 top
R37 "0" 0603 2750,3600 r0 top
R38 "0" 0603 1325,3275 r0 top
R39 "0" 0603 1725,3350 r90 top
R40 "390" 0603 2100,3325 r180 top
R41 "0" 0603 2225,3350 r270 top
R42 "47" 0603 2375,3350 r90 top
R43 "10K" 0603 2725,3350 r270 top
R44 "0" 0603 1325,3200 r0 top
R45 "10K" 0603 2725,3175 r90 top
R46 "0" 0603 1325,3125 r0 top
R47 "10K" 0603 3675,3125 r180 top
R48 "10K" 0603 3825,3125 r180 top
R49 "0" 0603 3675,3025 r180 top
R50 "do not fit" 0603 3825,3025 r0 top
R51 "4K7" RES4B 925,2925 r90 top
R52 "10K" 0603 3675,2925 r0 top
R53 "10K" 0603 3825,2925 r180 top
R54 "10K" 0603 3675,2825 r0 top
R55 "do not fit" 0603 3825,2825 r180 top
R56 "0" 0603 1650,2700 r180 top
R57 "do not fit" 0603 1825,2700 r0 top
R58 "10K" 0603 3675,2725 r0 top
R59 "10K" 0603 3825,2725 r180 top
R60 "0" 0603 3675,2625 r180 top
R61 "do not fit" 0603 3825,2625 r0 top
R62 "do not fit" 0603_NC 350,1900 r90 top
R63 "100K" 0603 2390,2975 r180 top
R64 "10K" 0603 3825,2525 r0 top
R65 "36K" 0603 625,2225 r90 top
R66 "47K" 0603 875,2225 r270 top
R67 "0" 0603 1975,2225 r180 top
R68 "0" 0603 2100,2225 r0 top
R69 "1.5K" 0603 400,3715 r90 top
R70 "10K" 0603 875,2075 r90 top
R71 "0" 0603 1625,2050 r180 top
R72 "10K" 0603 1625,2125 r180 top
R73 "10" 0603 2150,1900 r0 top
R74 "do not fit" 0603 2550,2025 r90 top
R75 "do not fit" 0603 2700,2025 r90 top
R76 "do not fit" 0603 2625,2025 r270 top
R77 "0" 0603 2775,2025 r270 top
R78 "do not fit" 0603 2875,2025 r270 top
R79 "0" 0603 2950,2025 r90 top
R80 "0" 0603 3025,2025 r270 top
R81 "0" 0603 350,4300 r270 top
R82 "0" 0603 425,4300 r270 top
R83 "10" 0603 1625,1650 r180 top
R84 "6.8" 0603 2150,1625 r90 top
R85 "47" 0603 3925,1000 r0 top
R86 "10" 0603 1975,1475 r90 top
R87 "6.8" 0603 2150,1475 r90 top
R88 "10K" 0603 3925,925 r180 top
R89 "0" 0603 3925,850 r180 top
R90 "4K7" 0603 900,1400 r0 top
R91 "10K" 0603 1625,1400 r180 top
R92 "5" 0603 3925,775 r0 top
R93 "10K" 0603 1625,1325 r180 top
R94 "0" 0603 1625,1250 r0 top
R95 "1M" 0603 250,4350 r180 top
R96 "600" 0603 2125,1100 r90 top
R97 "600" 0603 2050,1100 r90 top
R98 "600" 0603 1975,1100 r90 top
R99 "600" 0603 1900,1100 r90 top
R100 "0" 0603 2275,1100 r90 top
R101 "0" 0603 2350,1100 r90 top
R102 "0" 0603 2425,1100 r90 top
R103 "0" 0603 2500,1100 r90 top
R104 "0" 0603 2575,1100 r90 top
R105 "do not fit" 0603 3100,1100 r180 top
R106 "0" 0603 2775,950 r0 top
R107 "0" 0603 3100,1000 r180 top
R108 "10K" 0603 1625,850 r0 top
R109 "10K" 0603 1625,925 r180 top
R110 "330" 0603 1925,900 r0 top
R111 "0" 0603 2100,900 r0 top
R112 "10K" 0603 2275,875 r90 top
R113 "10K" 0603 2350,875 r270 top
R114 "10K" 0603 2425,875 r90 top
R115 "10K" 0603 2500,875 r90 top
R116 "10K" 0603 2575,875 r90 top
R117 "100" 0603 2775,875 r0 top
R118 "100K" 0603 900,800 r0 top
R119 "10K" 0603 900,725 r180 top
R120 "100" 0603 1925,700 r0 top
R121 "4K7" 0603 2100,700 r0 top
R122 "4K7" 0603 2775,725 r0 top
R123 "220K" 0603 1925,600 r0 top
R124 "100" 0603 2100,600 r0 top
R125 "100" 0603 2650,725 r270 top
R126 "0" 0603 3100,2575 r270 top
R127 "300" 0603 575,425 r270 top
R128 "0" 0603 1625,2200 r180 top
R129 "0" 0603 3825,2450 r0 top
R130 "47K" 0603 3500,2205 r0 top
R131 "47K" 0603 3500,2260 r0 top
R132 "47K" 0603 3500,1975 r0 top
R133 "47K" 0603 3500,2035 r0 top
R134 "47K" 0603 3500,2090 r0 top
R135 "0" 0603 1500,3350 r90 top
R136 "50" 0603 350,4525 r270 top
R137 "50" 0603 350,5175 r270 top
R138 "50" 0603 350,5825 r270 top
RV1 "10K" ADJRH 3725,475 r270 top
T1 "9013" SOT-23 750,2225 r180 top
T2 "9013" SOT-23 750,2075 r180 top
TP1 "Ground" TP 625,5975 r0 top
TP2 "Ground" TP 3325,5975 r0 top
TP3 "VREF" TP 2275,3225 r180 top
TP4 "5V" TP 1050,2825 r180 top
TP5 "3V3" TP 2375,2825 r0 top
TP6 "LIN" TP 2125,2625 r0 top
TP7 "MCKO" TP 2300,2625 r0 top
TP8 "HPR" TP 2525,2625 r0 top
TP9 "RIN" TP 2125,2450 r270 top
TP10 "HPL" TP 2325,2450 r0 top
TP11 "MCO" TP 2525,2450 r0 top
TP12 "SPP" TP 3250,475 r0 top
TP13 "SPN" TP 3375,475 r0 top
TP14 "AUX2" TP 775,400 r0 top
TP15 "AUX1" TP 900,400 r90 top
TP16 "Ground" TP 275,-25 r180 top
U1 "IS61WV51216BLL-10MLI" FBGA48(9*11) 2000,5125 r90 top
U2 "M29W128FL70ZA6E" TBGA64(10*13) 1425,5125 r0 top
U3 "NAND512W3A2DN6E" TSOP48 2450,4725 r90 top
U4 "SN65HVD230" SO8 2875,4175 r0 top
U5 "ST3232ECTR" TSSOP16 1000,4075 r90 top
U6 "M25P64-VME6G" VDFPN8(8*6) 2950,3725 r90 top
U7 "ST3232ECTR" TSSOP16 1000,3525 r90 top
U8 "STM32F103ZGT6" IC149-144-045-B5 2025,4025 r0 top locked
U9 "STLM75M2F" SO8 1025,3000 r0 top
U10 "AK4343" QFN32 1925,1700 r270 top
U11 "USBLC6-2P6" SOT-666 400,4025 r90 top
U12 "LD1086D2M33" D2PAK/A 725,1700 r0 top
U13 "TFDU4301-TR3" IR_VISHAY3 4075,825 r0 top
U14 "KSS-1508" KS1508 2700,1500 r0 top
U15 "ZEN056V130A24LS" polyzen 700,975 r180 top
U16 "BNX002-11" BNX001 50,850 r180 top
U17 "ST8024CDR" SO28 1050,1375 r0 top
U18 "HXM122032-GB1 (do not fit)" LCD12232-GB1 3525,725 r0 top
U19 "MT-11WW" JOY 2750,125 r45 top
X1 "8MHz (with socket)" XTAL_socket 2025,3075 r0 top
X2 "32KHz oscillator" SM8 1600,3080 r270 top
Z1 "SMAJ5.0A-TR" 1R1C 450,975 r0 top

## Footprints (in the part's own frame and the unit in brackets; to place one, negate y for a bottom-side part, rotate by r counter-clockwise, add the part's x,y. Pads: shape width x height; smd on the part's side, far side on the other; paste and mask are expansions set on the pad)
1R1C [mm]
  rect 1.75x2.3 smd: 1(0,-1.9) 2(0,1.9)
  silkscreen extent -1.5,-2.2 1.5,2.2
2*3P [mil]
  round 60 hole 40: 1(0,0) 2(100,0) 3(0,-100) 4(100,-100) 5(0,-200) 6(100,-200)
  silkscreen extent -50,-250 150,50
2*35P [mil]
  round 60 hole 40: 1(0,0) 2(100,0) 3(0,-100) 4(100,-100) 5(0,-200) 6(100,-200) 7(0,-300) 8(100,-300) 9(0,-400) 10(100,-400) 11(0,-500) 12(100,-500) 13(0,-600) 14(100,-600) 15(0,-700) 16(100,-700) 17(0,-800) 18(100,-800) 19(0,-900) 20(100,-900) 21(0,-1000) 22(100,-1000) 23(0,-1100) 24(100,-1100) 25(0,-1200) 26(100,-1200) 27(0,-1300) 28(100,-1300) 29(0,-1400) 30(100,-1400) 31(0,-1500) 32(100,-1500) 33(0,-1600) 34(100,-1600) 35(0,-1700) 36(100,-1700) 37(0,-1800) 38(100,-1800) 39(0,-1900) 40(100,-1900) 41(0,-2000) 42(100,-2000) 43(0,-2100) 44(100,-2100) 45(0,-2200) 46(100,-2200) 47(0,-2300) 48(100,-2300) 49(0,-2400) 50(100,-2400) 51(0,-2500) 52(100,-2500) 53(0,-2600) 54(100,-2600) 55(0,-2700) 56(100,-2700) 57(0,-2800) 58(100,-2800) 59(0,-2900) 60(100,-2900) 61(0,-3000) 62(100,-3000) 63(0,-3100) 64(100,-3100) 65(0,-3200) 66(100,-3200) 67(0,-3300) 68(100,-3300) 69(0,-3400) 70(100,-3400)
  silkscreen extent -50,-3450 150,50
0603 [mil]
  rect 30x30 smd: 1(-27.5,0) 2(27.5,0)
  silkscreen extent -50,-20 50,20
0603_NC [mil]
  rect 30x30 smd: 1(-27.5,0) 2(27.5,0)
  silkscreen extent -11,-10 9,10
0603P [mil]
  rect 30x30 smd: 1(-27.5,0) 2(27.5,0)
  silkscreen extent -50,-20 50,20
0603p [mil]
  rect 30x30 smd: 1(-27.5,0) 2(27.5,0)
  silkscreen extent -50,-20 50,20
0805 [mil]
  rect 50x40 smd: 1(0,40) 2(0,-40)
  silkscreen extent -35,-70 35,70
ADJRH [mil]
  round 118.11 hole 100: 0(-200,275) 0(200,275)
  round 80 hole 50: 1(-100,0) 2(0,0) 3(100,0)
  silkscreen extent -185,50 185,500
AM240*320B [mil]
  round 125.98 hole 125.98 unplated: 0(-3126.94,1.28) 0(-3126.94,1419) 0(0,0)
  round 60 hole 40: 1(-278,1464) 2(-178,1464) 3(-278,1364) 4(-178,1364) 5(-278,1264) 6(-178,1264) 7(-278,1164) 8(-178,1164) 9(-278,1064) 10(-178,1064) 11(-278,964) 12(-178,964) 13(-278,864) 14(-178,864) 15(-278,764) 16(-178,764) 17(-278,664) 18(-178,664) 19(-278,564) 20(-178,564) 21(-278,464) 22(-178,464) 23(-278,364) 24(-178,364) 25(-278,264) 26(-178,264) 27(-278,164) 28(-178,164) 29(-278,64) 30(-178,64)
  silkscreen extent -3225,-156 98,1574
BNX001 [mm]
  round 1.8 hole 1.4: 1(2.5,2.5) 2(-2.5,2.5) 3(2.5,-2.5) 4(0,0) 5(5,0) 6(-2.5,-2.5)
  silkscreen extent -5,-5 5.76,5
C160M [mil]
  rect 80x47.24 smd: 1(80,0) 2(-80,0)
  silkscreen extent -83,-83 83,83
C310M [mil]
  rect 200x120 smd paste-39.37 mask-39.37: 1(125,0) 2(-125,0)
  silkscreen extent -163,-163 163,163
D2PAK/A [mm]
  rect 2.8x1 smd: 1(11.4,-2.54) 2(11.4,0)
  rect 8x10.2 smd: 2(0,0)
  rect 2.8x1.42 smd: 3(11.4,2.54)
  silkscreen extent -4.06,-5.08 6.35,5.08
D0603 [mil]
  rect 30x30 smd: 1(0,27.5) 2(0,-27.5)
  silkscreen extent -25,-50 25,55
DB9/M [mil]
  round 50 hole 50: 0(-538,55) 0(-523,55) 0(-508,55) 0(-493,55) 0(-478,55) 0(-463,55) 0(-448,55) 0(448,55) 0(463,55) 0(478,55) 0(493,55) 0(508,55) 0(523,55) 0(538,55)
  oval 170x80 hole 50: 0(-493,55) 0(493,55)
  rect 70x80 hole 38: 1(218,0)
  oval 70x80 hole 38: 2(109,0) 3(0,0) 4(-109,0) 5(-218,0) 6(164,110) 7(55,110) 8(-54,110) 9(-163,110)
  silkscreen extent -618,-100 618,410
DC10B [mil]
  round 45 hole 30: 1(244.09,-40) 1(244.09,-20) 1(244.09,20) 1(244.09,40) 2(82.05,-196.85) 2(102.05,-196.85) 2(142.05,-196.85) 2(162.05,-196.85) 3(0,-40) 3(0,-20) 3(0,20) 3(0,40)
  oval 80x180 hole 30: 1(244.1,0) 3(0,0)
  oval 180x80 hole 30: 2(122.05,-196.85)
  silkscreen extent -175,-170 290,180
FBGA48(9*11) [mil]
  round 12 smd: A1(-73.82,103.35) A2(-44.29,103.35) A3(-14.76,103.35) A4(14.76,103.35) A5(44.29,103.35) A6(73.82,103.35) B1(-73.82,73.82) B2(-44.29,73.82) B3(-14.76,73.82) B4(14.76,73.82) B5(44.29,73.82) B6(73.82,73.82) C1(-73.82,44.29) C2(-44.29,44.29) C3(-14.76,44.29) C4(14.76,44.29) C5(44.29,44.29) C6(73.82,44.29) D1(-73.82,14.76) D2(-44.29,14.76) D3(-14.76,14.76) D4(14.76,14.76) D5(44.29,14.76) D6(73.82,14.76) E1(-73.82,-14.76) E2(-44.29,-14.76) E3(-14.76,-14.76) E4(14.76,-14.76) E5(44.29,-14.76) E6(73.82,-14.76) F1(-73.82,-44.29) F2(-44.29,-44.29) F3(-14.76,-44.29) F4(14.76,-44.29) F5(44.29,-44.29) F6(73.82,-44.29) G1(-73.82,-73.82) G2(-44.29,-73.82) G3(-14.76,-73.82) G4(14.76,-73.82) G5(44.29,-73.82) G6(73.82,-73.82) H1(-73.82,-103.35) H2(-44.29,-103.35) H3(-14.76,-103.35) H4(14.76,-103.35) H5(44.29,-103.35) H6(73.82,-103.35)
  TopLayer lines w5: -157.48,216.54 -177.17,216.54 -177.17,196.85 ; 157.48,216.54 177.17,216.54 177.17,196.85 ; -177.17,-196.85 -177.17,-216.54 -157.48,-216.54 ; 177.17,-196.85 177.17,-216.54 157.48,-216.54
  silkscreen extent -158,167 -138,187
FTSH-110-01-L-DV [mil]
  round 38 hole 38 unplated: 0(-200,0) 0(200,0)
  rect 29x110 smd: 1(-225,-80) 2(-225,80) 3(-175,-80) 4(-175,80) 5(-125,-80) 6(-125,80) 7(-75,-80) 8(-75,80) 9(-25,-80) 10(-25,80) 11(25,-80) 12(25,80) 13(75,-80) 14(75,80) 15(125,-80) 16(125,80) 17(175,-80) 18(175,80) 19(225,-80) 20(225,80)
  silkscreen extent -275,-100 275,100
IC149-144-045-B5 [mm]
  rect 1x2.5 smd rot 45: 0(-11,-11) 0(11,11)
  rect 1x2.5 smd rot 135: 0(-11,11) 0(11,-11)
  round 1.5 hole 1.5 unplated: 0(0,-8) 0(0,8)
  rect 0.22x1.6 smd: 1(-8.75,-10.9) 2(-8.25,-10.9) 3(-7.75,-10.9) 4(-7.25,-10.9) 5(-6.75,-10.9) 6(-6.25,-10.9) 7(-5.75,-10.9) 8(-5.25,-10.9) 9(-4.75,-10.9) 10(-4.25,-10.9) 11(-3.75,-10.9) 12(-3.25,-10.9) 13(-2.75,-10.9) 14(-2.25,-10.9) 15(-1.75,-10.9) 16(-1.25,-10.9) 17(-0.75,-10.9) 18(-0.25,-10.9) 19(0.25,-10.9) 20(0.75,-10.9) 21(1.25,-10.9) 22(1.75,-10.9) 23(2.25,-10.9) 24(2.75,-10.9) 25(3.25,-10.9) 26(3.75,-10.9) 27(4.25,-10.9) 28(4.75,-10.9) 29(5.25,-10.9) 30(5.75,-10.9) 31(6.25,-10.9) 32(6.75,-10.9) 33(7.25,-10.9) 34(7.75,-10.9) 35(8.25,-10.9) 36(8.75,-10.9) 73(8.75,10.9) 74(8.25,10.9) 75(7.75,10.9) 76(7.25,10.9) 77(6.75,10.9) 78(6.25,10.9) 79(5.75,10.9) 80(5.25,10.9) 81(4.75,10.9) 82(4.25,10.9) 83(3.75,10.9) 84(3.25,10.9) 85(2.75,10.9) 86(2.25,10.9) 87(1.75,10.9) 88(1.25,10.9) 89(0.75,10.9) 90(0.25,10.9) 91(-0.25,10.9) 92(-0.75,10.9) 93(-1.25,10.9) 94(-1.75,10.9) 95(-2.25,10.9) 96(-2.75,10.9) 97(-3.25,10.9) 98(-3.75,10.9) 99(-4.25,10.9) 100(-4.75,10.9) 101(-5.25,10.9) 102(-5.75,10.9) 103(-6.25,10.9) 104(-6.75,10.9) 105(-7.25,10.9) 106(-7.75,10.9) 107(-8.25,10.9) 108(-8.75,10.9)
  rect 1.6x0.22 smd: 37(10.9,-8.75) 38(10.9,-8.25) 39(10.9,-7.75) 40(10.9,-7.25) 41(10.9,-6.75) 42(10.9,-6.25) 43(10.9,-5.75) 44(10.9,-5.25) 45(10.9,-4.75) 46(10.9,-4.25) 47(10.9,-3.75) 48(10.9,-3.25) 49(10.9,-2.75) 50(10.9,-2.25) 51(10.9,-1.75) 52(10.9,-1.25) 53(10.9,-0.75) 54(10.9,-0.25) 55(10.9,0.25) 56(10.9,0.75) 57(10.9,1.25) 58(10.9,1.75) 59(10.9,2.25) 60(10.9,2.75) 61(10.9,3.25) 62(10.9,3.75) 63(10.9,4.25) 64(10.9,4.75) 65(10.9,5.25) 66(10.9,5.75) 67(10.9,6.25) 68(10.9,6.75) 69(10.9,7.25) 70(10.9,7.75) 71(10.9,8.25) 72(10.9,8.75) 109(-10.9,8.75) 110(-10.9,8.25) 111(-10.9,7.75) 112(-10.9,7.25) 113(-10.9,6.75) 114(-10.9,6.25) 115(-10.9,5.75) 116(-10.9,5.25) 117(-10.9,4.75) 118(-10.9,4.25) 119(-10.9,3.75) 120(-10.9,3.25) 121(-10.9,2.75) 122(-10.9,2.25) 123(-10.9,1.75) 124(-10.9,1.25) 125(-10.9,0.75) 126(-10.9,0.25) 127(-10.9,-0.25) 128(-10.9,-0.75) 129(-10.9,-1.25) 130(-10.9,-1.75) 131(-10.9,-2.25) 132(-10.9,-2.75) 133(-10.9,-3.25) 134(-10.9,-3.75) 135(-10.9,-4.25) 136(-10.9,-4.75) 137(-10.9,-5.25) 138(-10.9,-5.75) 139(-10.9,-6.25) 140(-10.9,-6.75) 141(-10.9,-7.25) 142(-10.9,-7.75) 143(-10.9,-8.25) 144(-10.9,-8.75)
  silkscreen extent -10.29,-10.29 10.29,10.29
IDC14S [mil]
  round 60 hole 40: 1(0,0) 2(100,0) 3(0,-100) 4(100,-100) 5(0,-200) 6(100,-200) 7(0,-300) 8(100,-300) 9(0,-400) 10(100,-400) 11(0,-500) 12(100,-500) 13(0,-600) 14(100,-600)
  silkscreen extent -125,-800 237,200
IDC20S [mil]
  round 60 hole 40: 1(0,0) 2(100,0) 3(0,-100) 4(100,-100) 5(0,-200) 6(100,-200) 7(0,-300) 8(100,-300) 9(0,-400) 10(100,-400) 11(0,-500) 12(100,-500) 13(0,-600) 14(100,-600) 15(0,-700) 16(100,-700) 17(0,-800) 18(100,-800) 19(0,-900) 20(100,-900)
  silkscreen extent -125,-1100 250,200
IDC34S [mil]
  round 60 hole 40: 1(0,0) 2(100,0) 3(0,-100) 4(100,-100) 5(0,-200) 6(100,-200) 7(0,-300) 8(100,-300) 9(0,-400) 10(100,-400) 11(0,-500) 12(100,-500) 13(0,-600) 14(100,-600) 15(0,-700) 16(100,-700) 17(0,-800) 18(100,-800) 19(0,-900) 20(100,-900) 21(0,-1000) 22(100,-1000) 23(0,-1100) 24(100,-1100) 25(0,-1200) 26(100,-1200) 27(0,-1300) 28(100,-1300) 29(0,-1400) 30(100,-1400) 31(0,-1500) 32(100,-1500) 33(0,-1600) 34(100,-1600)
  silkscreen extent -125,-1800 250,200
IR_VISHAY3 [mm]
  rect 2x0.5 smd: 1(0,0) 2(0,0.95) 3(0,1.9) 4(0,2.85) 5(0,3.8) 6(0,4.75) 7(0,5.7) 8(0,6.65)
  silkscreen extent -1.1,-1 4.17,7.5
JOY [mm]
  round 0.7 hole 0.7 unplated: 0(0,1.9)
  round 1 hole 1 unplated: 0(0,-1.9)
  rect 1.778x1.016 smd: 1(-3.1,1.4) 2(-3.1,0) 3(-3.1,-1.4) 4(3.1,-1.4) 5(3.1,0) 6(3.1,1.4)
  silkscreen extent -3.8,-3.7 3.8,4.1
JP2_SMD [mm]
  rect 0.4x0.4 smd: 1(-0.3,0) 2(0.3,0)
  silkscreen extent -0.75,-0.45 0.75,0.45
KS1508 [mil]
  round 60 hole 40: 1(-149.61,0) 2(149.61,0)
  silkscreen extent -295,-295 295,295
LCD12232-GB1 [mil]
  round 125.98 hole 125.98 unplated: 0(-3129.92,0) 0(0,0)
  round 60 hole 30: 1(-1153.94,1475) 2(-1053.94,1475) 3(-953.94,1475) 4(-853.94,1475) 5(-753.94,1475) 6(-653.94,1475) 7(-553.94,1475) 8(-453.94,1475)
  silkscreen extent -3230,-157 98,1575
LI1220_1 [mm]
  round 1.1 hole 1.1 unplated: 0(0,3.75)
  round 1.5 hole 1.5 unplated: 0(0.025,-3.75)
  oct 2.5x6 smd: 1(0,-8.6)
  oval 2.5x6 smd: 2(0,8.6)
  silkscreen extent -7.62,-7.57 7.62,7.57
MSD(PJS008) [mm]
  round 0.7 hole 0.7 unplated: 0(0,0) 0(0,7.55)
  rect 1.6x0.8 smd: 1(-5.8,1.475) 2(-5.8,2.575) 3(-5.8,3.675) 4(-5.8,4.775) 5(-5.8,5.875) 6(-5.8,6.975) 7(-5.8,8.075) 8(-5.8,9.175)
  rect 1.6x0.85 smd: 9(-5.8,10.325)
  rect 1.4x1.95 smd: 10(4.4,11.225)
  rect 3.5x1.6 smd: G1(-3.65,-3.4)
  rect 3.1x1.5 smd: G2(7.35,11.45)
  rect 3.5x1.4 smd: G3(7.35,-3.5)
  rect 3.1x1.2 smd: G4(-4.15,11.6)
  silkscreen extent -5.07,-3.81 9.28,11.43
PB10 [mil]
  rect 40x60 smd: 1(-87.5,177.17) 2(87.5,177.17) 3(87.5,-177.17) 4(-87.5,-177.17)
  silkscreen extent -125,-125 125,125
polyzen [mm]
  rect 0.8x2.21 smd: 1(0,0)
  rect 0.7x0.94 smd: 2(3.429,0.635) 3(3.429,-0.635)
  silkscreen extent -0.38,-2.03 3.68,2.03
QFN32 [mm]
  rect 2.5x2.5 smd: 0(0,0)
  rect 0.7x0.2 smd: 1(-2.4,1.75) 2(-2.4,1.25) 3(-2.4,0.75) 4(-2.4,0.25) 5(-2.4,-0.25) 6(-2.4,-0.75) 7(-2.4,-1.25) 8(-2.4,-1.75) 17(2.4,-1.75) 18(2.4,-1.25) 19(2.4,-0.75) 20(2.4,-0.25) 21(2.4,0.25) 22(2.4,0.75) 23(2.4,1.25) 24(2.4,1.75)
  rect 0.2x0.7 smd: 9(-1.75,-2.4) 10(-1.25,-2.4) 11(-0.75,-2.4) 12(-0.25,-2.4) 13(0.25,-2.4) 14(0.75,-2.4) 15(1.25,-2.4) 16(1.75,-2.4) 25(1.75,2.4) 26(1.25,2.4) 27(0.75,2.4) 28(0.25,2.4) 29(-0.25,2.4) 30(-0.75,2.4) 31(-1.25,2.4) 32(-1.75,2.4)
  silkscreen extent -2.79,-2.79 2.79,2.79
RES4B [mil]
  rect 15.75x35 smd: 1(47.24,33.5) 2(47.24,-33.5) 3(15.75,33.5) 4(15.75,-33.5) 5(-15.75,33.5) 6(-15.75,-33.5) 7(-47.24,33.5) 8(-47.24,-33.5)
  silkscreen extent -70,-28 70,28
SAM(C816) [mm]
  rect 1.5x1.3 smd: 1(-12.3,-8.255) 2(-12.3,-5.715) 3(-12.3,-3.175) 4(-12.3,-0.635) 5(12.3,-8.255) 6(12.3,-5.715) 7(12.3,-3.175) 8(12.3,-0.635)
  rect 1.75x1 smd: 17(-5.5,4.445) 18(-5.5,6.985)
  round 2 hole 2.2 unplated: G0(-10.16,22.225) G0(10.16,-22.225)
  silkscreen extent -17.15,-29.59 14.61,26.42
SIP2 [mil]
  round 60 hole 40: 1(0,0) 2(100,0)
  silkscreen extent -50,-50 150,50
SIP3 [mil]
  rect 60x60 hole 40: 1(0,0)
  round 60 hole 40: 2(100,0) 3(200,0)
  silkscreen extent -50,-50 50,50
SM8 [mm]
  rect 1.9x1.3 smd: 1(-2.75,-1.6) 2(2.75,-1.6) 3(2.75,1.6) 4(-2.75,1.6)
  silkscreen extent -4.44,-1.91 4.44,1.91
SO8 [mil]
  rect 24x76 smd: 1(0,0) 2(50,0) 3(100,0) 4(150,0) 5(150,225) 6(100,225) 7(50,225) 8(0,225)
  silkscreen extent -30,60 180,160
SO28 [mil]
  rect 75x25 smd: 1(0,0) 2(0,-50) 3(0,-100) 4(0,-150) 5(0,-200) 6(0,-250) 7(0,-300) 8(0,-350) 9(0,-400) 10(0,-450) 11(0,-500) 12(0,-550) 13(0,-600) 14(0,-650) 15(400,-650) 16(400,-600) 17(400,-550) 18(400,-500) 19(400,-450) 20(400,-400) 21(400,-350) 22(400,-300) 23(400,-250) 24(400,-200) 25(400,-150) 26(400,-100) 27(400,-50) 28(400,0)
  silkscreen extent 80,-685 320,35
SOT-23 [mil]
  rect 36x36 smd: 1(37.5,-40) 2(-37.5,-40)
  rect 36x50 smd: 3(0.5,40)
  silkscreen extent -58,-45 58,45
SOT-666 [mm]
  rect 1.16x0.279 smd: 1(-0.795,0.5) 2(-0.795,0) 3(-0.795,-0.5) 4(0.795,-0.5) 5(0.795,0) 6(0.795,0.5)
  silkscreen extent -0.82,-0.88 0.82,0.88
ST-225-02 [mm]
  round 2 hole 1.2: 1(0,0.254) 1(0,0) 1(0,-0.254) 2(2.3,1.746) 2(2.3,2.254) 3(7.8,1.746) 3(7.8,2) 3(7.8,2.235)
  round 2 hole 1.4: 2(2.3,2)
  silkscreen extent -4.41,-5 13.05,3.5
TAN-A [mil]
  rect 50x60 smd: 1(-55,0) 2(55,0)
  silkscreen extent -105,-45 95,45
TAN-B [mil]
  rect 50x100 smd: 1(-60,0) 2(60,0)
  silkscreen extent -120,-75 110,75
TBGA64(10*13) [mil]
  round 12 smd: A1(-137.8,137.8) A2(-98.43,137.8) A3(-59.06,137.8) A4(-19.69,137.8) A5(19.68,137.8) A6(59.06,137.8) A7(98.43,137.8) A8(137.8,137.8) B1(-137.8,98.43) B2(-98.43,98.43) B3(-59.06,98.43) B4(-19.69,98.43) B5(19.68,98.43) B6(59.06,98.43) B7(98.43,98.43) B8(137.8,98.43) C1(-137.8,59.06) C2(-98.43,59.06) C3(-59.06,59.06) C4(-19.69,59.06) C5(19.68,59.06) C6(59.06,59.06) C7(98.43,59.06) C8(137.8,59.06) D1(-137.8,19.69) D2(-98.43,19.69) D3(-59.06,19.69) D4(-19.68,19.68) D5(19.68,19.69) D6(59.06,19.69) D7(98.43,19.69) D8(137.8,19.69) E1(-137.8,-19.68) E2(-98.43,-19.68) E3(-59.06,-19.68) E4(-19.68,-19.68) E5(19.68,-19.68) E6(59.06,-19.68) E7(98.43,-19.68) E8(137.8,-19.68) F1(-137.8,-59.06) F2(-98.43,-59.06) F3(-59.06,-59.06) F4(-19.69,-59.06) F5(19.68,-59.06) F6(59.06,-59.06) F7(98.43,-59.06) F8(137.8,-59.06) G1(-137.8,-98.43) G2(-98.43,-98.43) G3(-59.06,-98.43) G4(-19.69,-98.43) G5(19.68,-98.43) G6(59.06,-98.43) G7(98.43,-98.43) G8(137.8,-98.43) H1(-137.8,-137.8) H2(-98.43,-137.8) H3(-59.06,-137.8) H4(-19.69,-137.8) H5(19.68,-137.8) H6(59.06,-137.8) H7(98.43,-137.8) H8(137.8,-137.8)
  TopLayer lines w5: -196.85,-255.91 -196.85,-236.22 ; -196.85,236.22 -196.85,255.91 -177.17,255.91 ; 177.17,-255.91 196.85,-255.91 196.85,-236.22 ; 177.17,255.91 196.85,255.91 196.85,236.22
  silkscreen extent -158,187 -138,207
TP [mil]
  round 60 hole 40: 1(0,0)
  silkscreen extent -45,-45 45,45
TSOP48 [mil]
  rect 40x9 smd: 1(0,0) 2(0,-19.68) 3(0,-39.37) 4(0,-59.06) 5(0,-78.74) 6(0,-98.43) 7(0,-118.11) 8(0,-137.8) 9(0,-157.48) 10(0,-177.17) 11(0,-196.85) 12(0,-216.54) 13(0,-236.22) 14(0,-255.91) 15(0,-275.59) 16(0,-295.28) 17(0,-314.96) 18(0,-334.65) 19(0,-354.33) 20(0,-374.02) 21(0,-393.7) 22(0,-413.39) 23(0,-433.07) 24(0,-452.76) 25(787.4,-452.76) 26(787.4,-433.07) 27(787.4,-413.39) 28(787.4,-393.7) 29(787.4,-374.02) 30(787.4,-354.33) 31(787.4,-334.65) 32(787.4,-314.96) 33(787.4,-295.28) 34(787.4,-275.59) 35(787.4,-255.91) 36(787.4,-236.22) 37(787.4,-216.54) 38(787.4,-196.85) 39(787.4,-177.17) 40(787.4,-157.48) 41(787.4,-137.8) 42(787.4,-118.11) 43(787.4,-98.43) 44(787.4,-78.74) 45(787.4,-59.06) 46(787.4,-39.37) 47(787.4,-19.68) 48(787.4,0)
  silkscreen extent 50,-463 738,10
TSSOP16 [mm]
  rect 1.15x0.3 smd: 1(0,0) 2(0,-0.65) 3(0,-1.3) 4(0,-1.95) 5(0,-2.6) 6(0,-3.25) 7(0,-3.9) 8(0,-4.55) 9(6.4,-4.55) 10(6.4,-3.9) 11(6.4,-3.25) 12(6.4,-2.6) 13(6.4,-1.95) 14(6.4,-1.3) 15(6.4,-0.65) 16(6.4,0)
  silkscreen extent 0.94,-4.88 5.42,0.33
USB-B [mil]
  round 120 hole 95: 0(-291,-185) 0(189,-185)
  round 50 hole 30: 1(0,0) 2(-98,0) 3(-98,-80) 4(0,-80)
  silkscreen extent -365,-488 263,57
VB334 [mm]
  round 2 hole 1.3: 1(-3.125,3.125) 2(3.125,3.125) 3(3.125,-3.125) 4(-3.125,-3.125)
  round 2.032 hole 1.27: 5(0,0)
  silkscreen extent -5.5,-5.5 5.5,5.5
VDFPN8(8*6) [mm]
  rect 2.54x4.064 smd: 0(0,0)
  rect 1x0.5 smd: 1(-3.81,1.905) 2(-3.81,0.635) 3(-3.81,-0.635) 4(-3.81,-1.905) 5(3.81,-1.905) 6(3.81,-0.635) 7(3.81,0.635) 8(3.81,1.905)
  silkscreen extent -4,-3.04 4,3.01
XTAL_socket [mil]
  round 80 hole 53: 1(100,0) 2(-100,0)
  silkscreen extent -215,-89 214,89

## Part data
B1 B2 B3 B4: library part "SW PUSHBUTTON", "SE PUSHBUTTON"
BOOT0 BOOT1: library part SW-SPDT, "SPDT Subminiature Toggle Switch, Right Angle Mounting, Vertical Actuation"
BT1: library part BATTERY, "Battery"
C1 C2 C3 C4 C5 C6 C7 C9 C10 C13 C15 C20 C21 C22 C24 C49 C51 C60 C62 C63 C75 C88: library part cap, "Capacitor"
C8 C12 C14 C16 C17 C18 C19 C23 C25 C26 C27 C28 C29 C30 C31 C32 C33 C34 C35 C36 C37 C38 C39 C40 C41 C42 C43 C44 C47 C48 C52 C54 C55 C58 C64 C66 C67 C68 C72 C74 C76 C78 C83 C85 C86 C87 C89 C90 C91 C92 C93 C94 C95 C96 C97 C98 C99 C100: library part CAP, "Capacitor"
C11 C45 C46: library part Cap, "Capacitor"
C50 C53 C56 C57 C59 C61 C65 C69 C70 C71 C73 C77 C79 C80 C81 C82 C84: library part "Cap Pol1", "Polarized Capacitor (Radial)"
CN2 CN3 CN5: library part "Header 5", "Header, 5-Pin"
CN4 CN8 CN12: library part DB9
CN6: "Header, 7-Pin, Dual row"
CN7 CN9: library part 20PIN1
CN10 CN11: library part Header35X2
CN13: library part SMS016AFA5E
CN14: library part USB-B, "USB-B"
CN15: library part ST-225-02
CN16: library part ColorLCD_module
CN17: library part PJ202A
CN18: library part Smart_card_CN
JP1 JP4 JP7 JP8 JP14 JP18: library part Jumper3
JP2 JP3 JP5 JP6 JP11 JP12 JP15 JP16 JP17 JP19 JP20 JP21 JP22: library part JP2
JP9 JP10 JP23 JP24 JP25 JP26 JP27: library part "Circuit Breaker", "Circuit Breaker"
JP13: library part "Header 3X2", "Header, 3-Pin, Dual row"
L1: library part Inductor, "Inductor"
LD1 LD2 LD3 LD4 LD5: library part LED2, "Typical RED, GREEN, YELLOW, AMBER GaAs LED"
R1 R3 R4 R5 R6 R7 R8 R11 R12 R13 R14 R15 R16 R17 R18 R19 R20 R21 R22 R23 R24 R25 R29 R30 R32 R34 R35 R36 R37 R38 R39 R40 R41 R42 R44 R46 R47 R48 R49 R50 R52 R53 R54 R55 R58 R59 R60 R61 R63 R64 R66 R71 R74 R75 R76 R77 R78 R79 R80 R81 R82 R88 R89 R90 R91 R93 R94 R95 R96 R97 R98 R99 R100 R101 R102 R103 R104 R105 R106 R107 R108 R109 R110 R111 R112 R113 R114 R115 R116 R117 R118 R120 R124 R125 R126 R129 R130 R131 R132 R133 R134 R135 R136 R137 R138: library part Res1, "Resistor"
R2 R9 R10 R26 R27 R28 R31 R33 R43 R45 R56 R57 R62 R67 R68 R72 R73 R83 R84 R86 R87 R119 R121 R122 R123 R127 R128: library part res1, "Resistor"
R51: library part RES4B
R65 R70: library part R
R69 R85 R92: library part RES1
RV1: library part RV
T1 T2: library part NPN
TP1 TP2 TP3 TP4 TP5 TP6 TP7 TP8 TP9 TP10 TP11 TP12 TP13 TP14 TP15 TP16: library part TP
U1: library part IS64WV51216BLL-10MA3
U3: library part NAND01GW3B2BN, "1G/8bits/3.3V/large page/"
U4: library part SN65HVD230D
U5 U7: library part ST3232, "3.3V/5V Dual RS232 Transceiver w/ Int. Cap."
U8: library part BigPiranha_new
U9: library part STLM75DW2F
U11: library part USBLC6-2
U12: library part VOLTREG1
U13: library part TFDU4300, "TFDU4300"
U14: library part Speaker, "Loudspeaker"
U16: library part BNX002
U17: library part ST8024CTR
U18: library part HXM122032-GB1
U19: library part MT-008A
X1: library part CRYSTAL, "Crystal"
X2: library part MC306
Z1: library part "D Schottky", "Schottky Diode"

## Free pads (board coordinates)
  round 137.8 hole 137.8 unplated: 0(0,0) 0(0,6350) 0(4050,0) 0(4050,6350)
  round 30 smd: 0(360,100) 0(1170,4825) 0(1550,3550) 0(1700,5375) 0(2215,4880) 0(2500,4525) 0(3485,6000)

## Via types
v1: diameter 16, hole 8, TopLayer to BottomLayer, tented both sides, 621 vias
